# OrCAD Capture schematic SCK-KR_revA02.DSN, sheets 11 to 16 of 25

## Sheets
11 PMOD3&4: size Custom
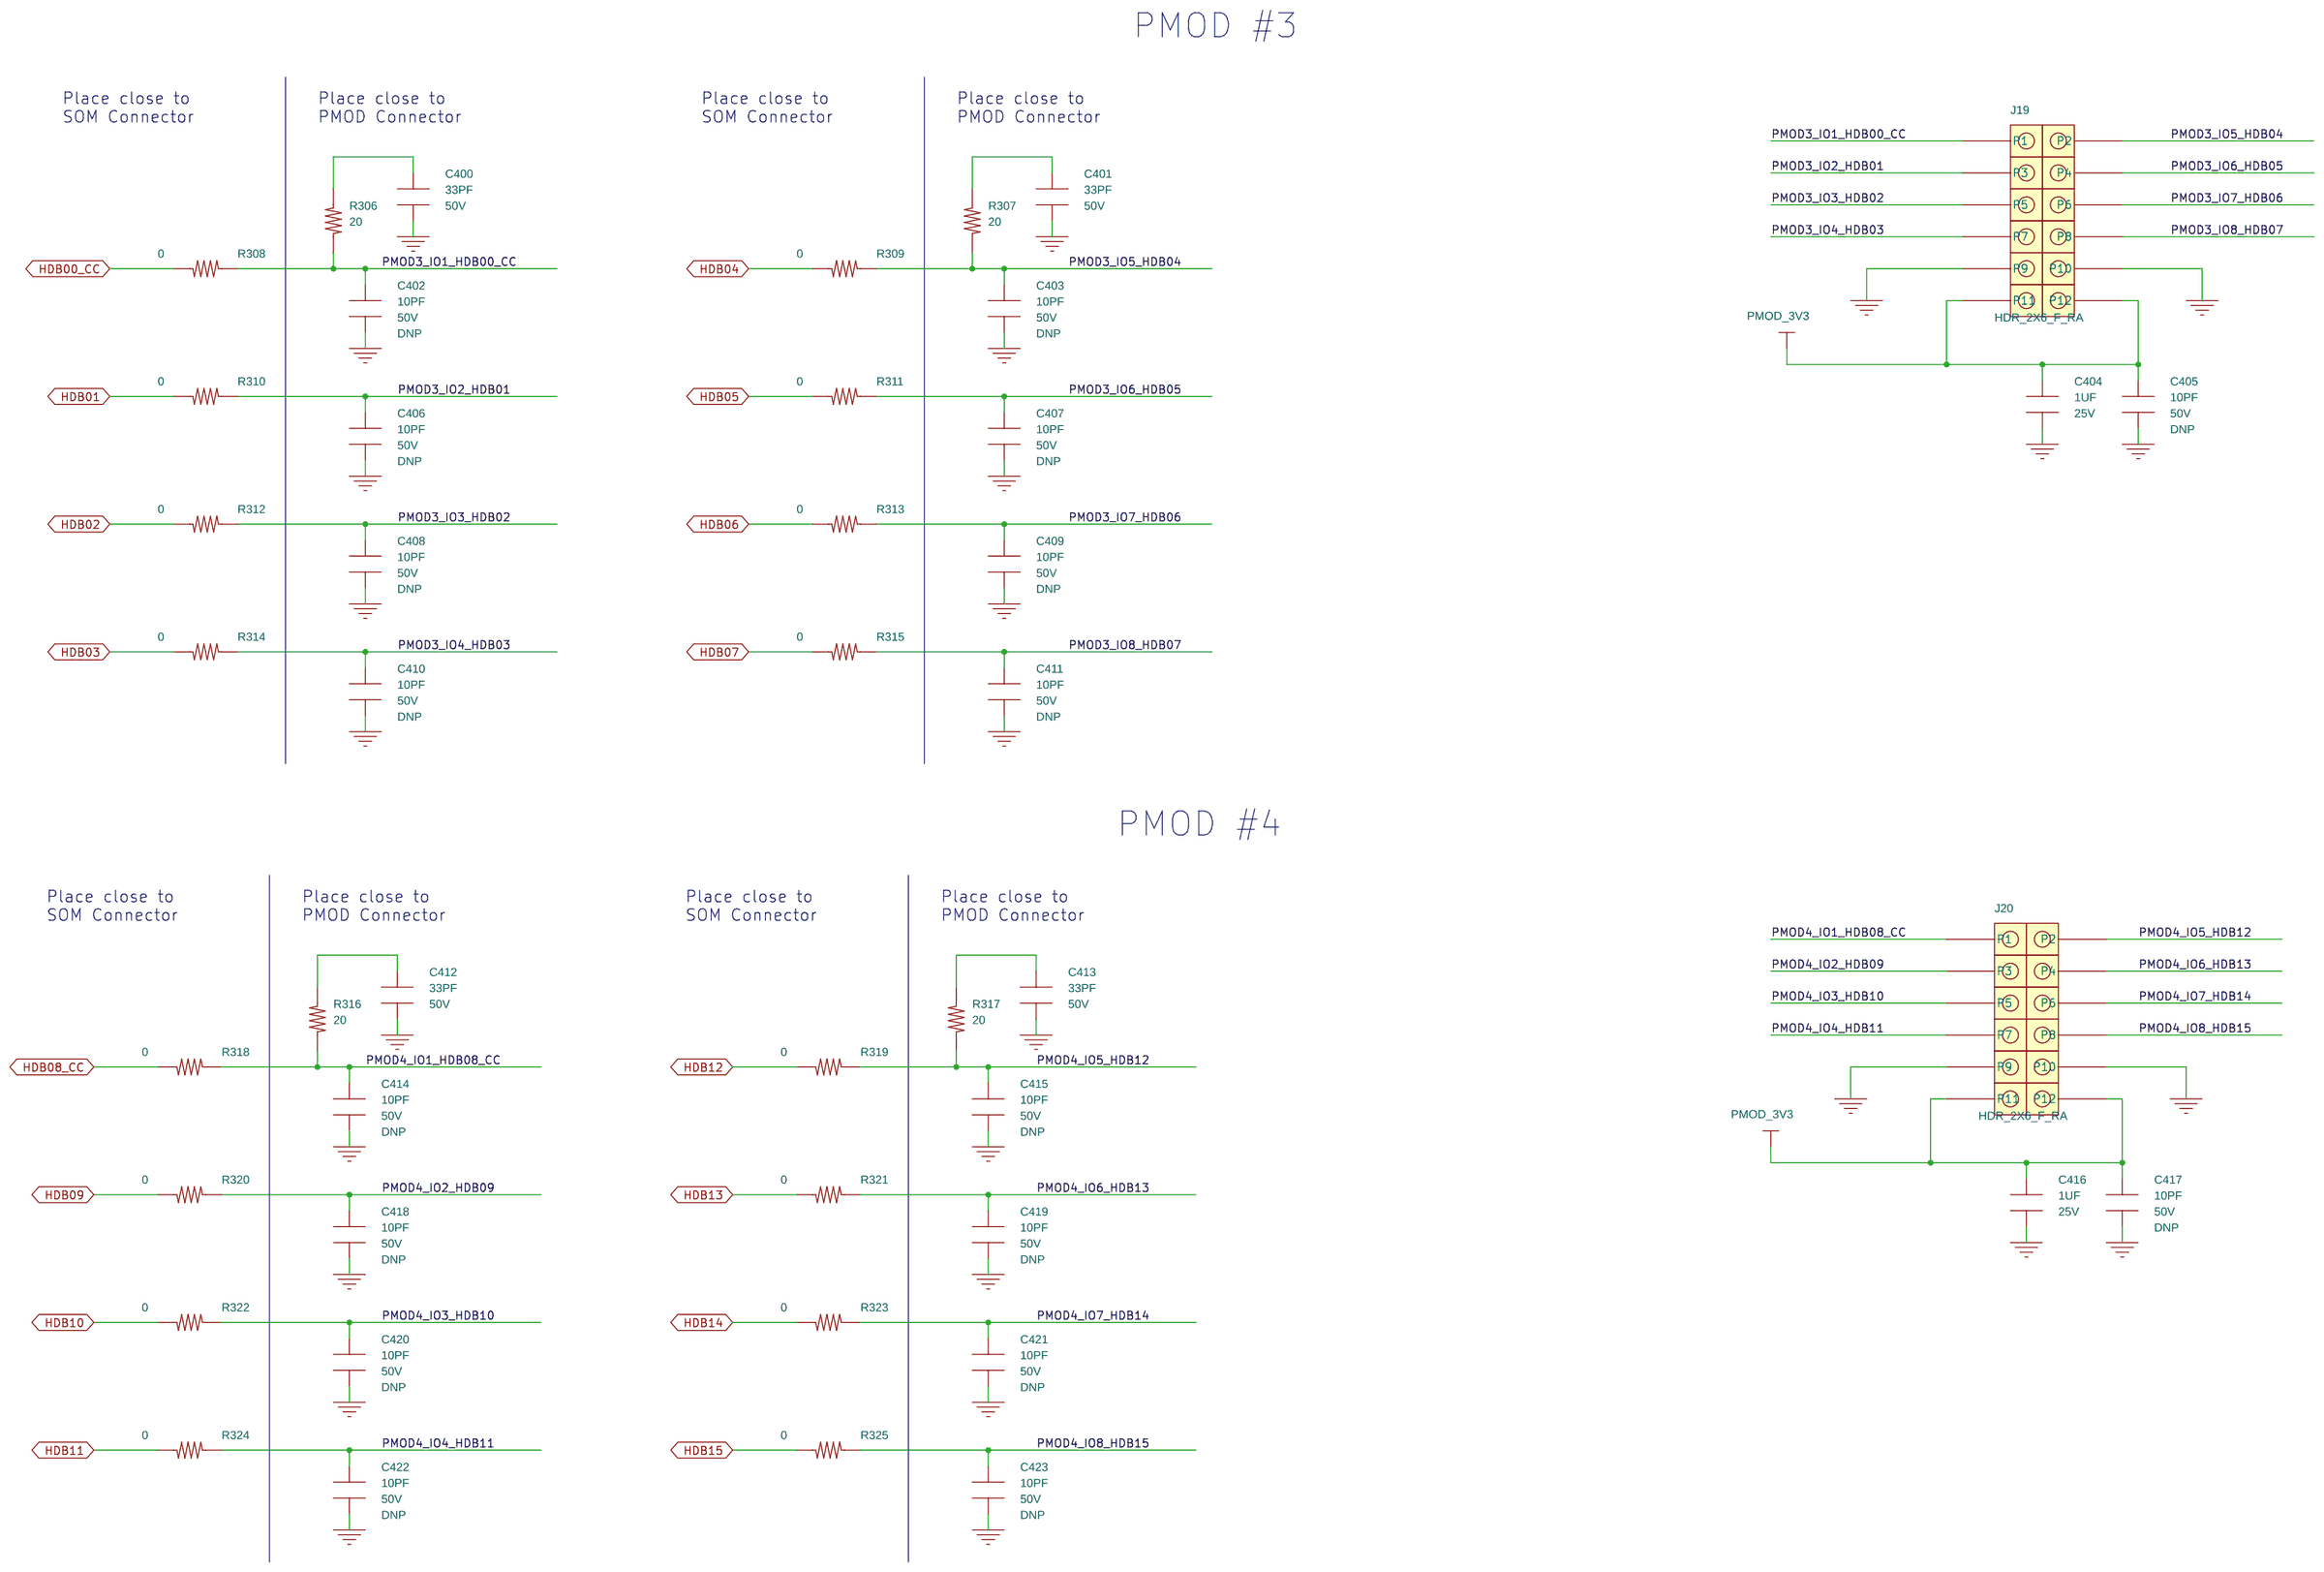
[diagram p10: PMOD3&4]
12 RPI Expansion CONN: size Custom
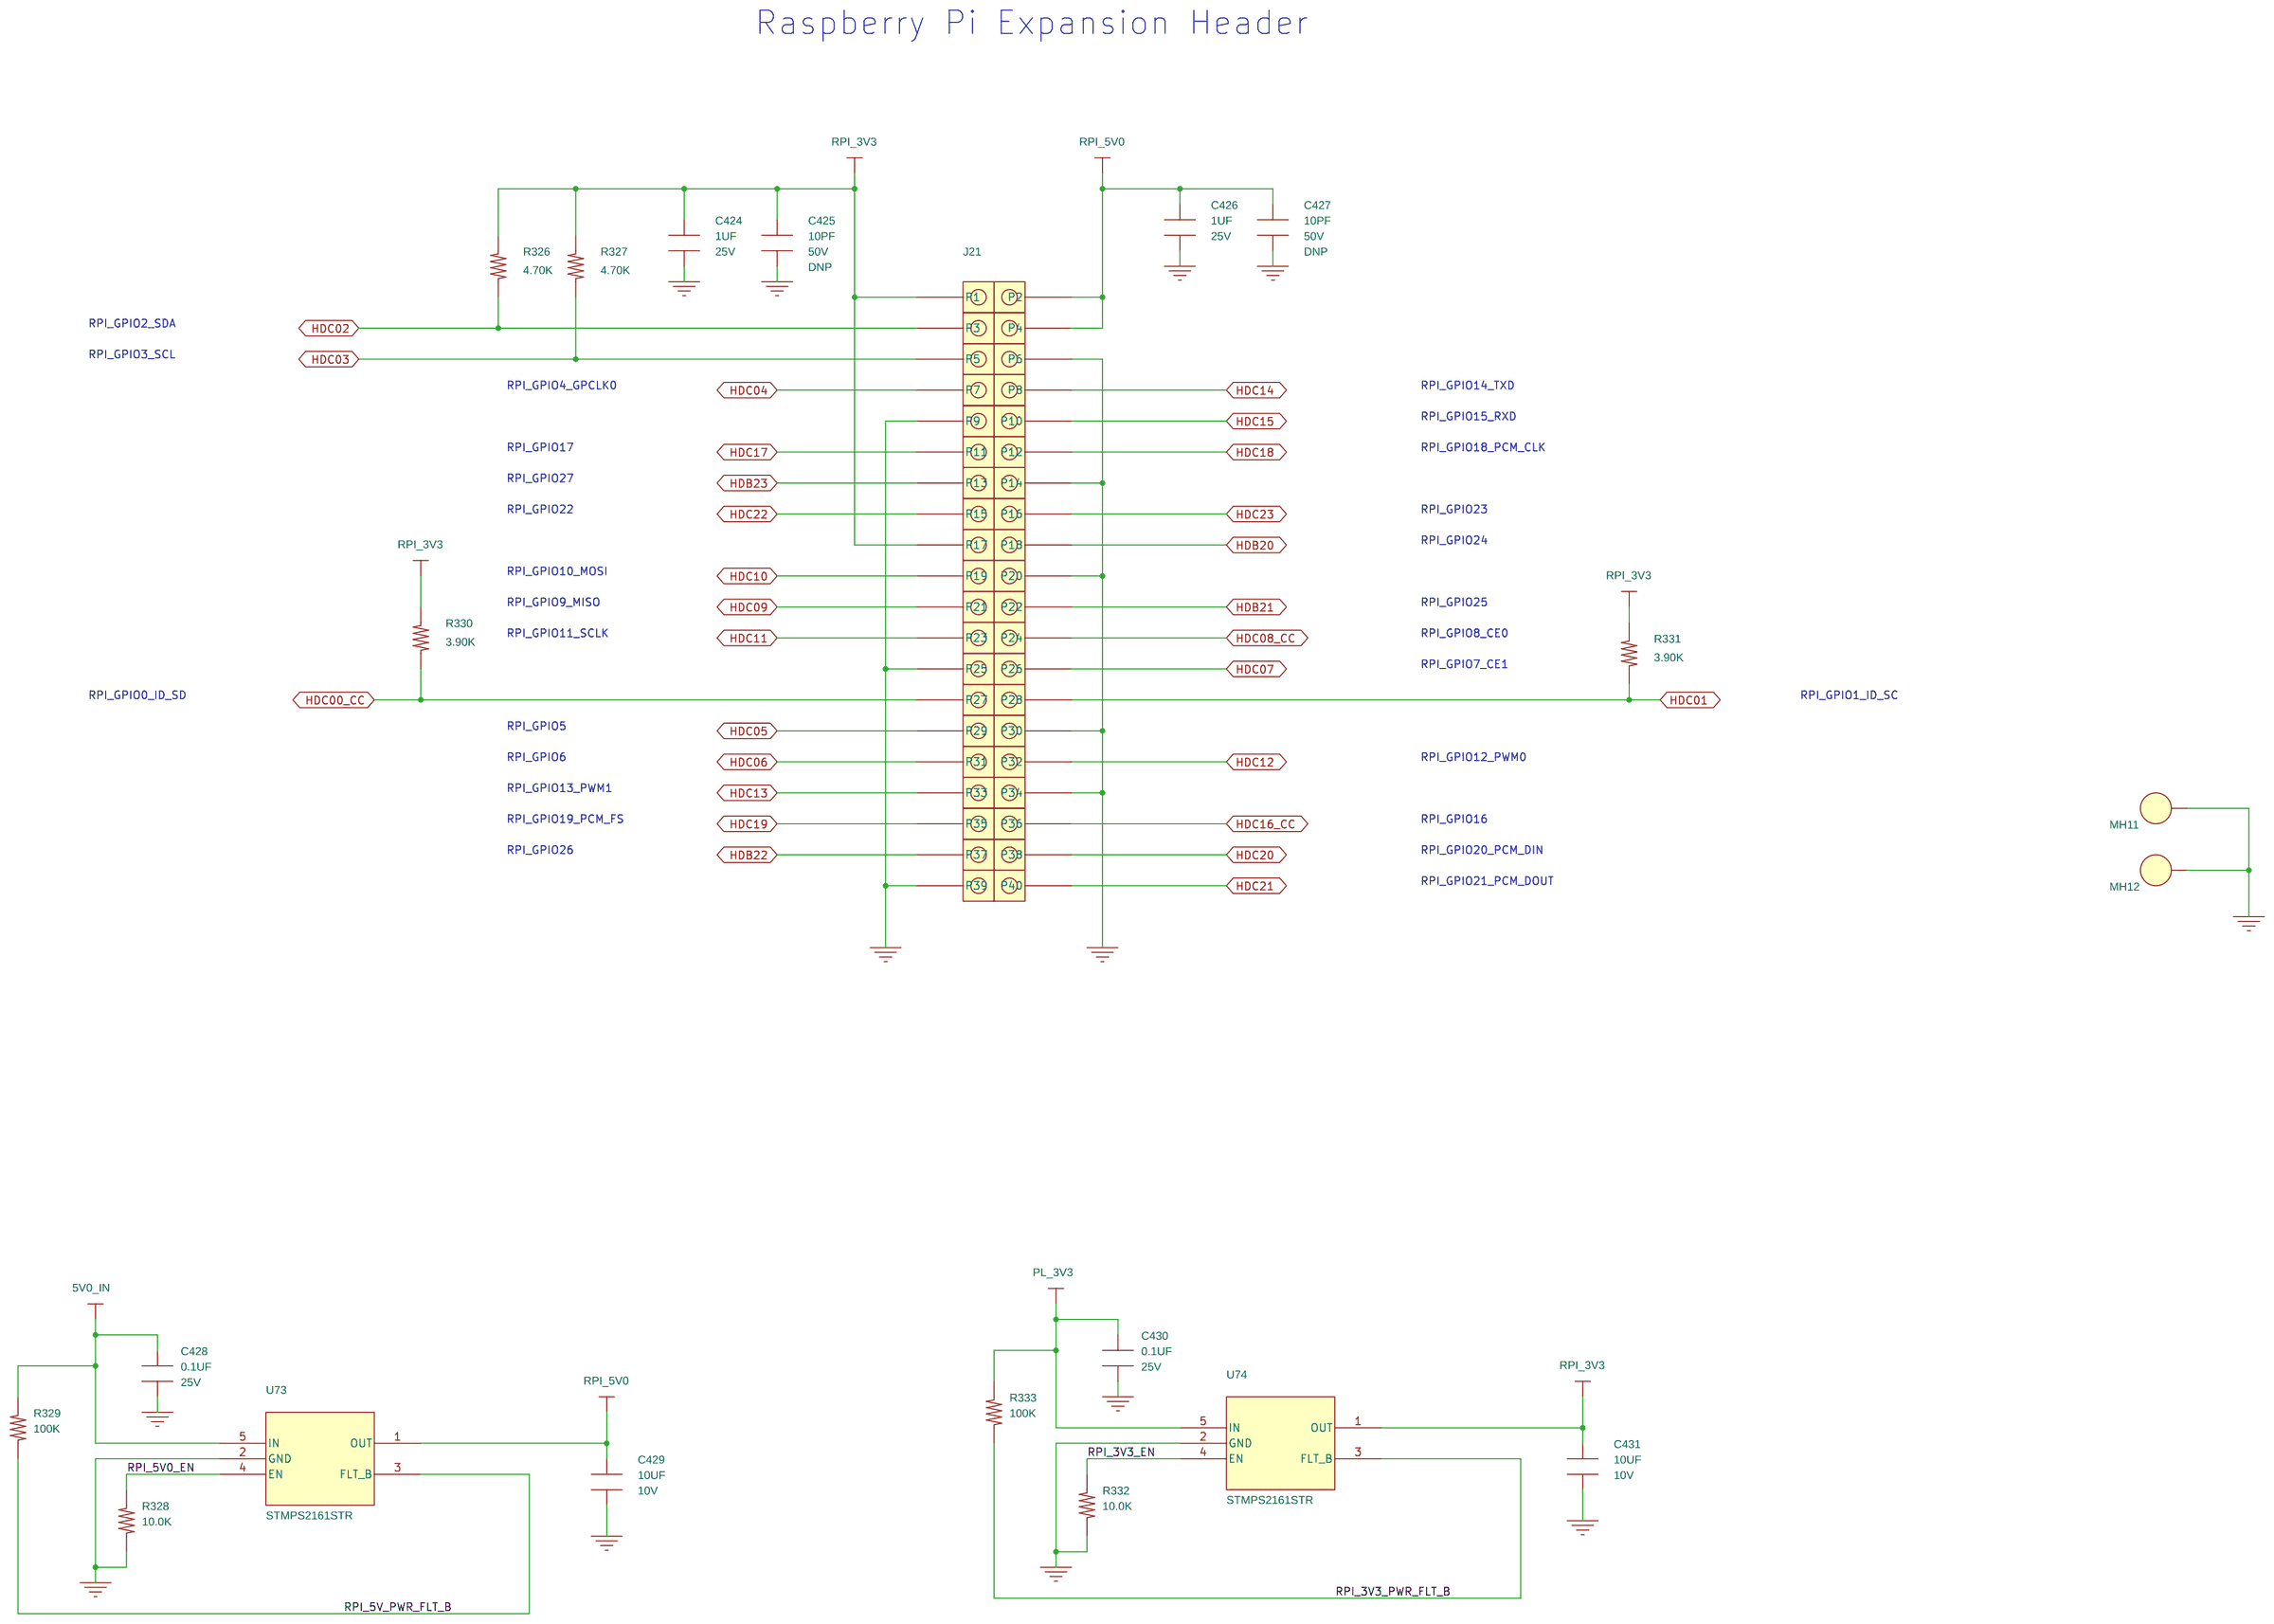
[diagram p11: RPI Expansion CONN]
13 Framos CONN: size Custom
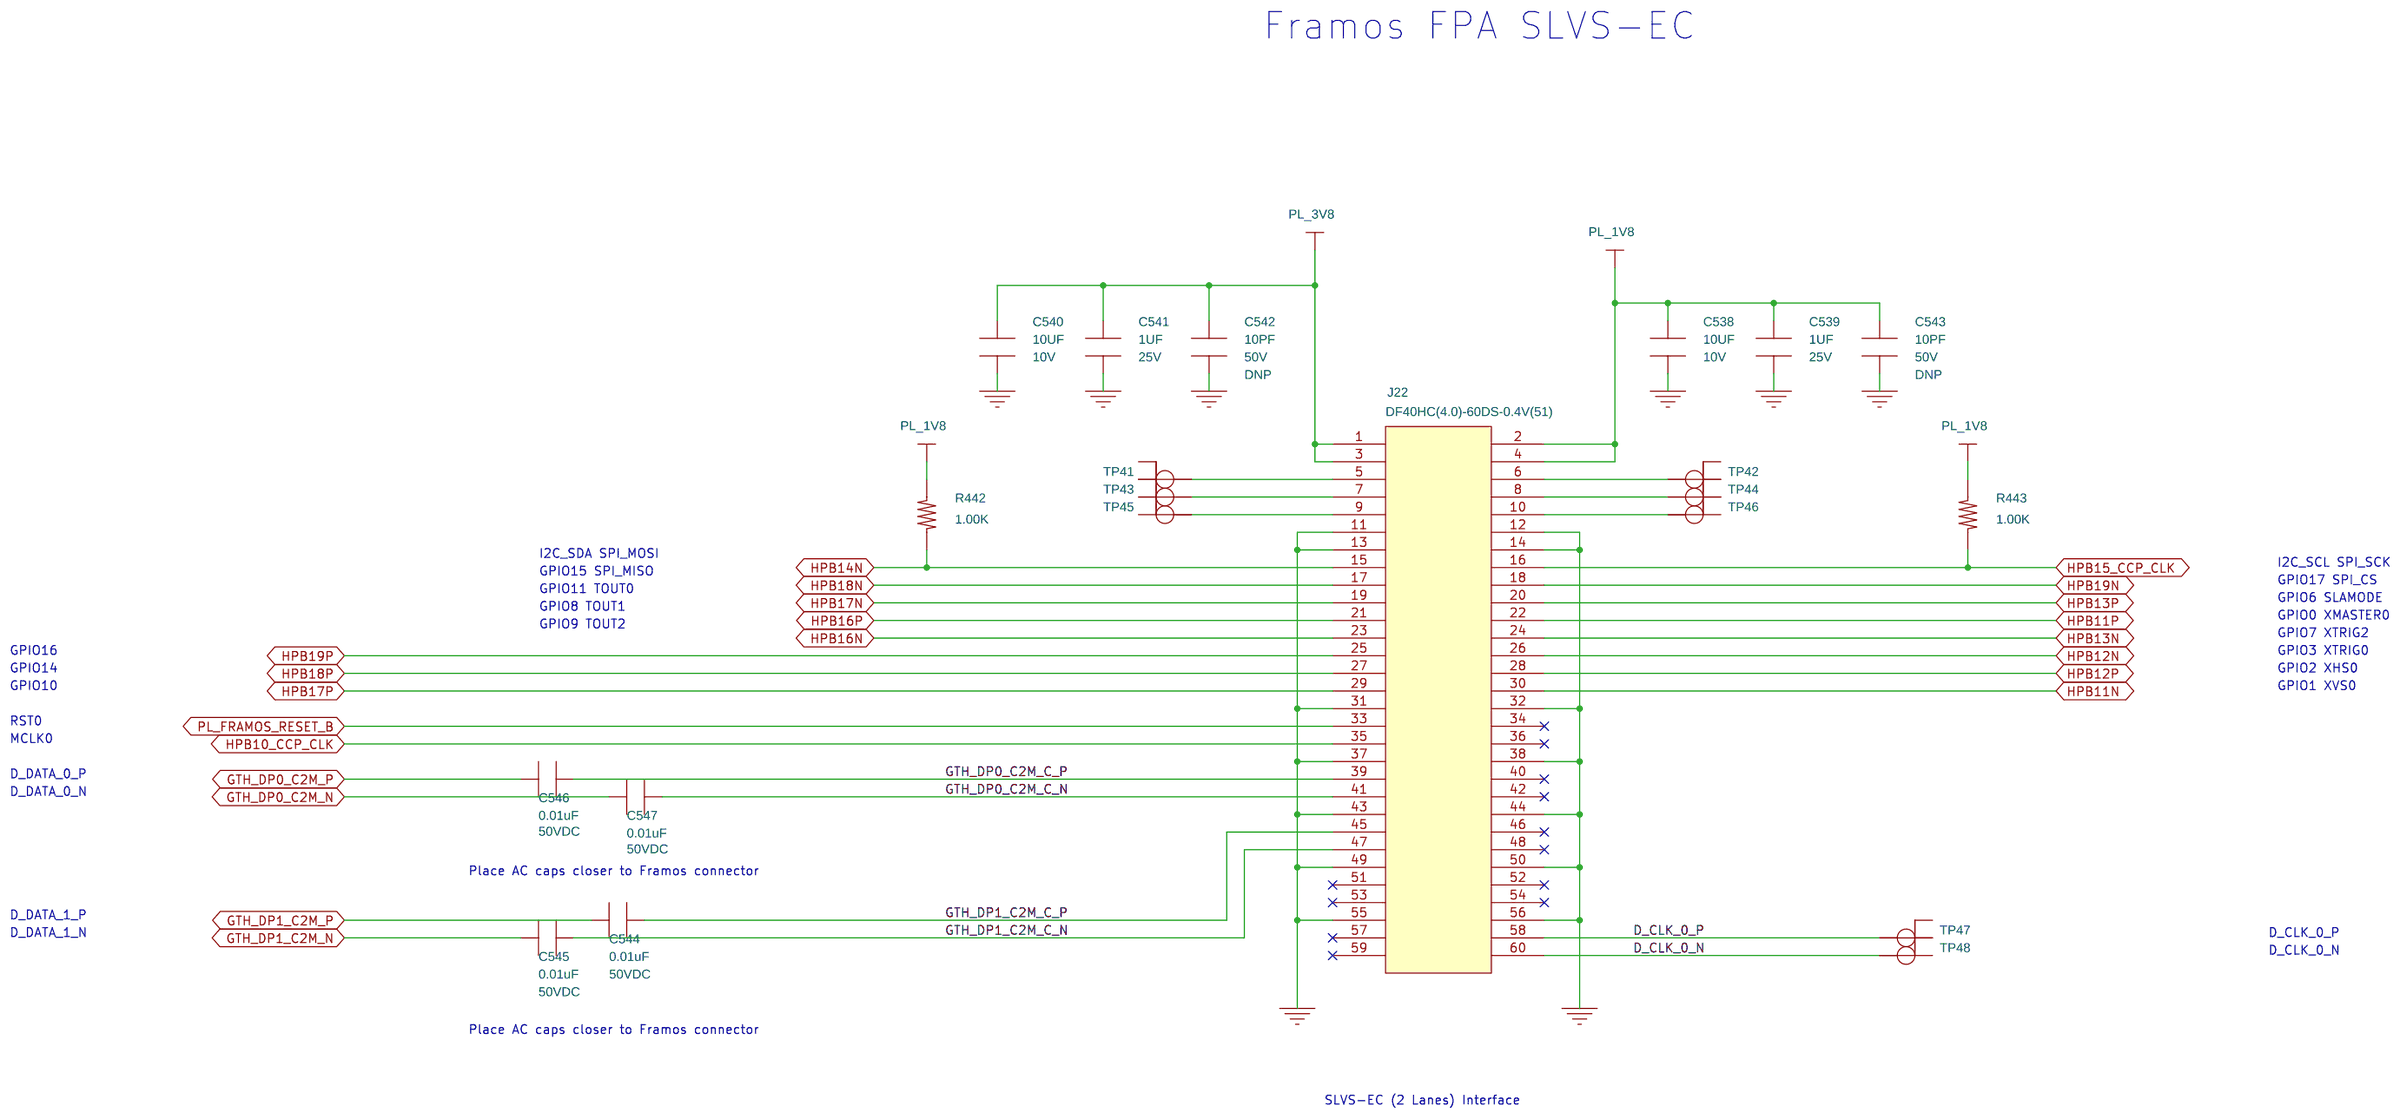
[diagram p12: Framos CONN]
14 SFP+: size Custom
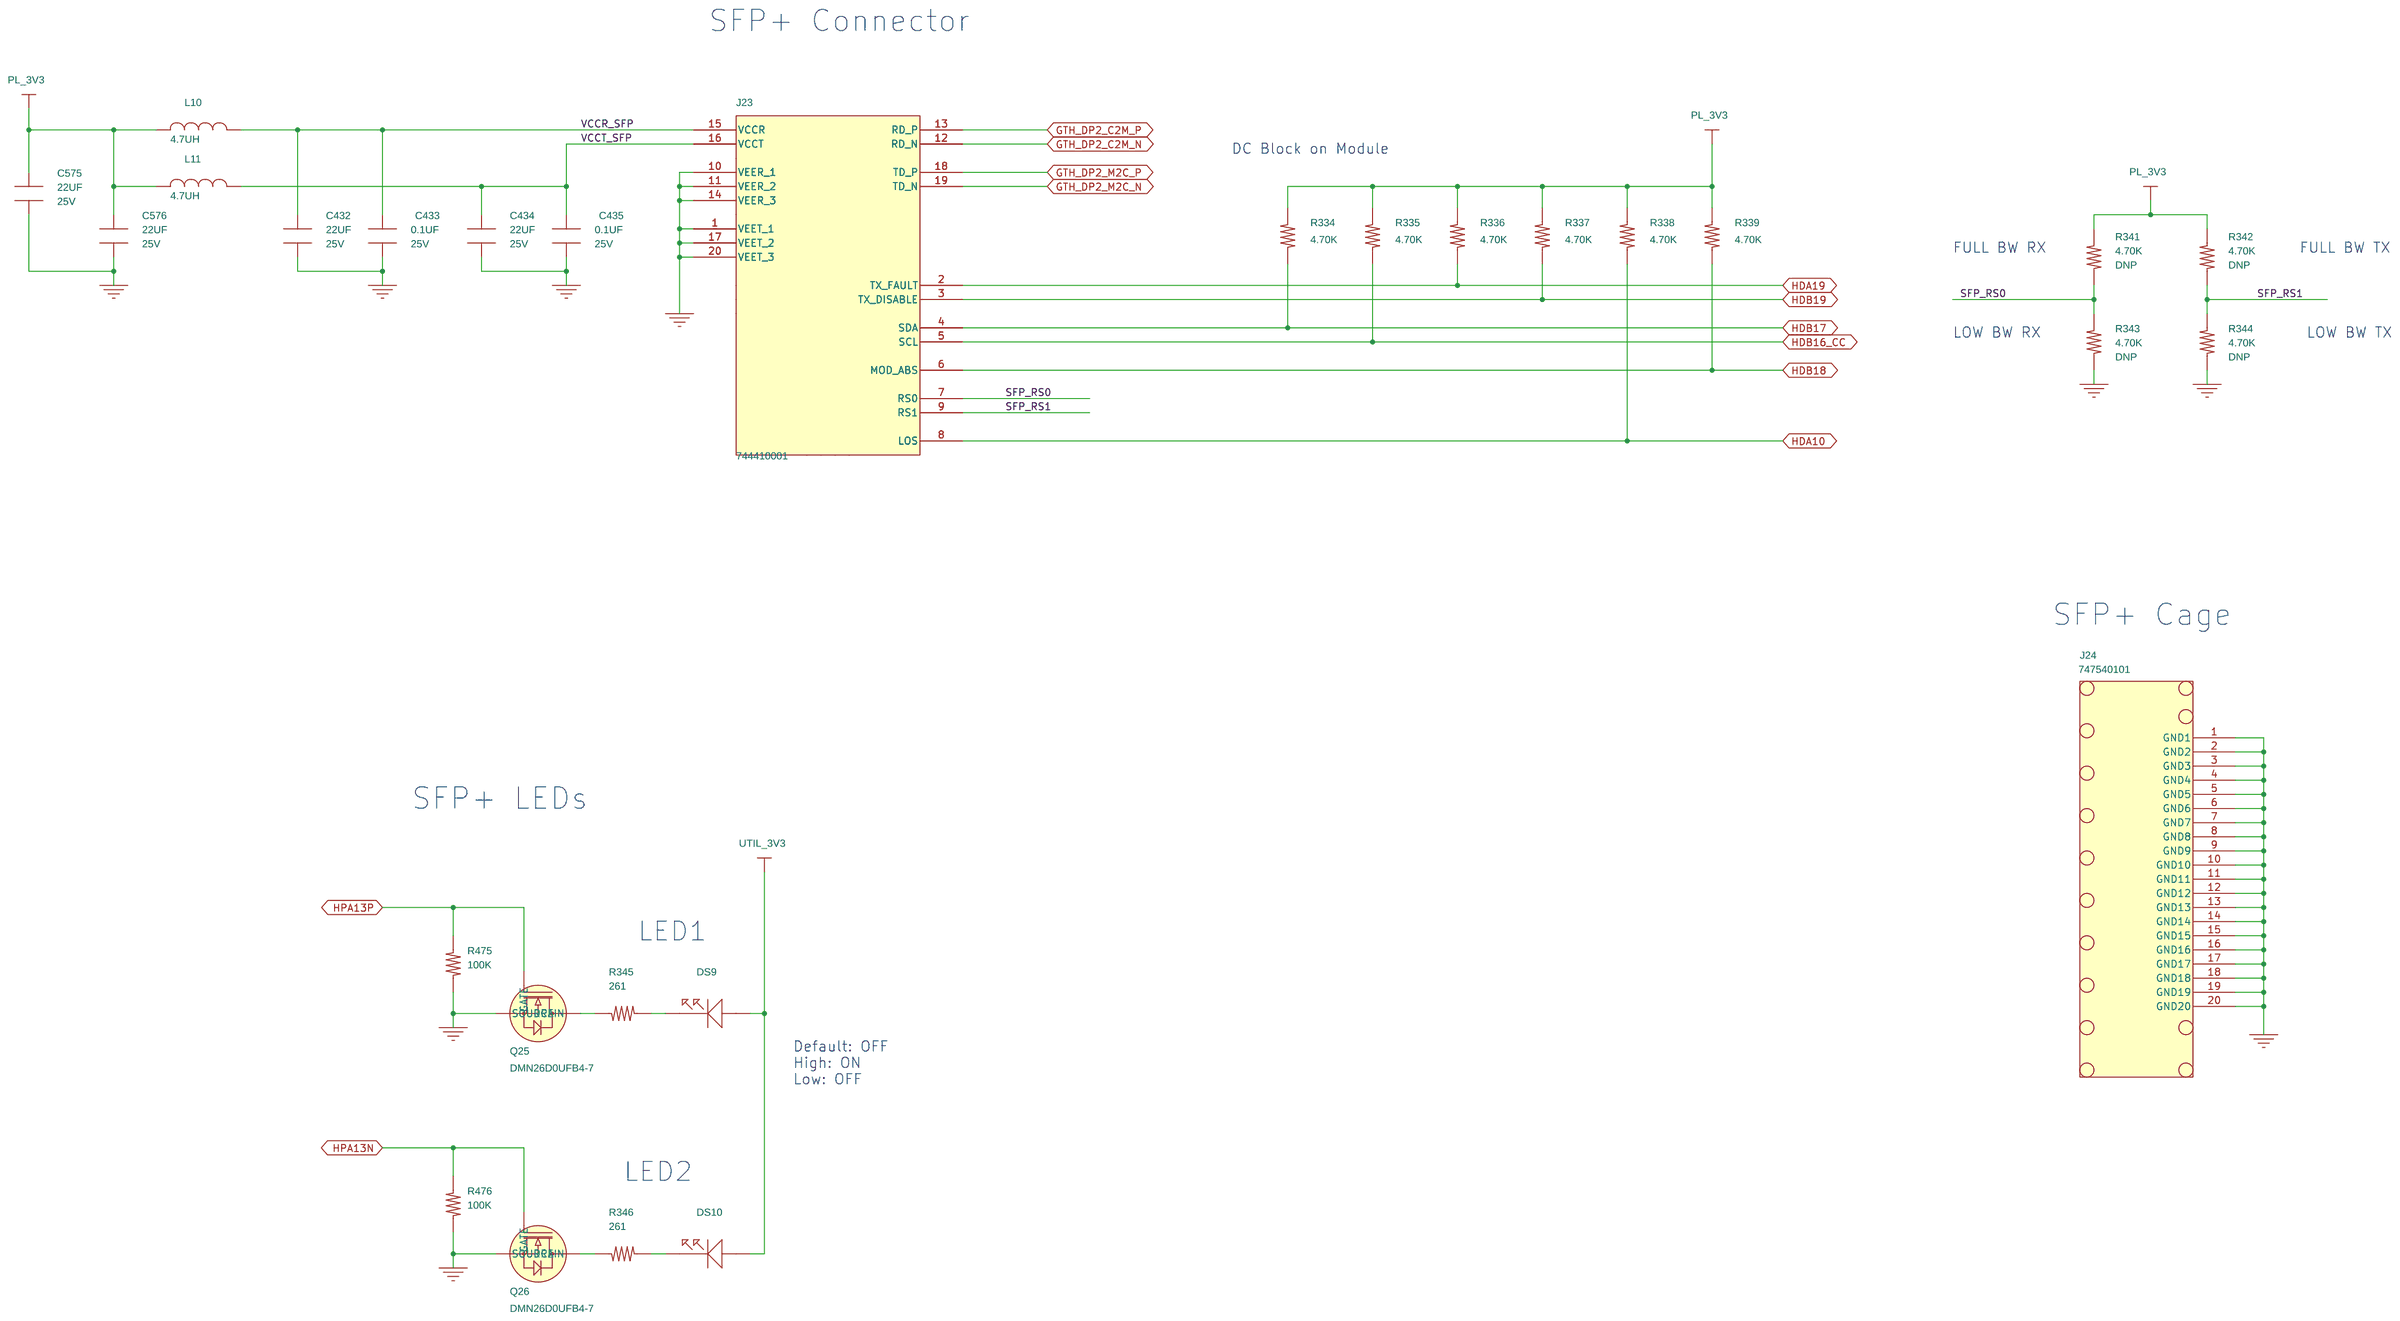
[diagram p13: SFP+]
15 I2C, EEPROM: size Custom
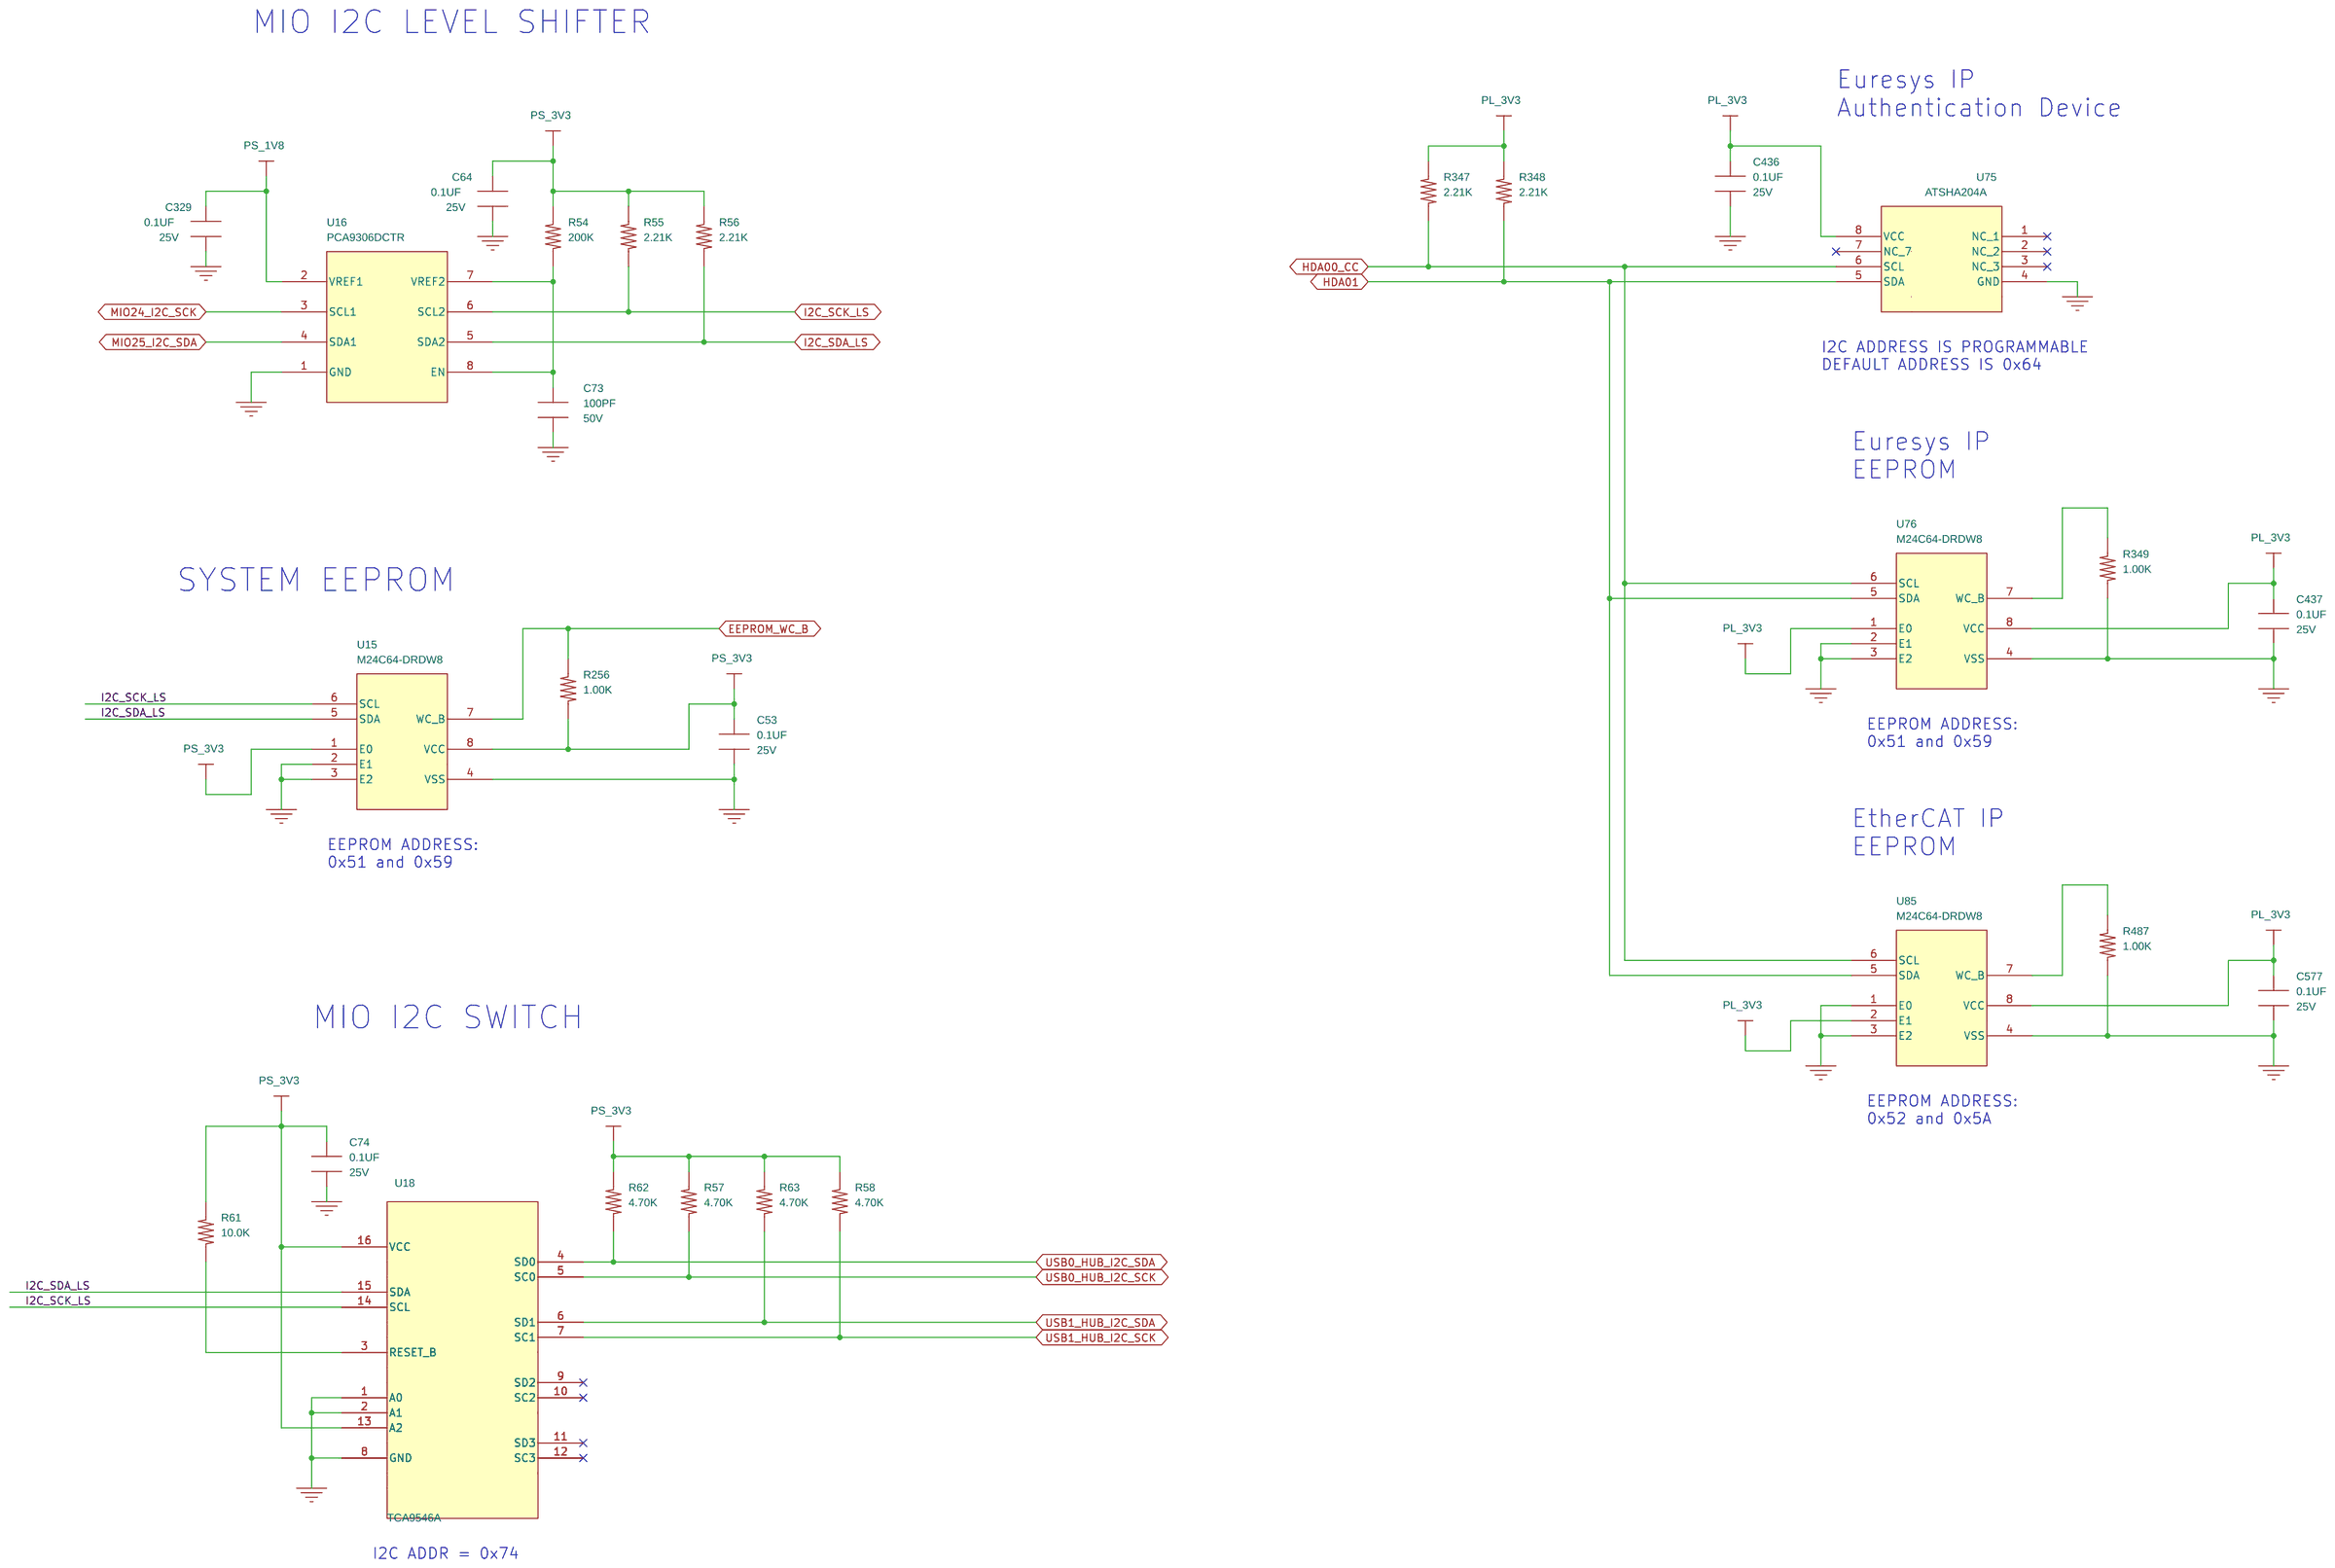
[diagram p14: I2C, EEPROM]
16 16_Clock Gen, Reset: size Custom
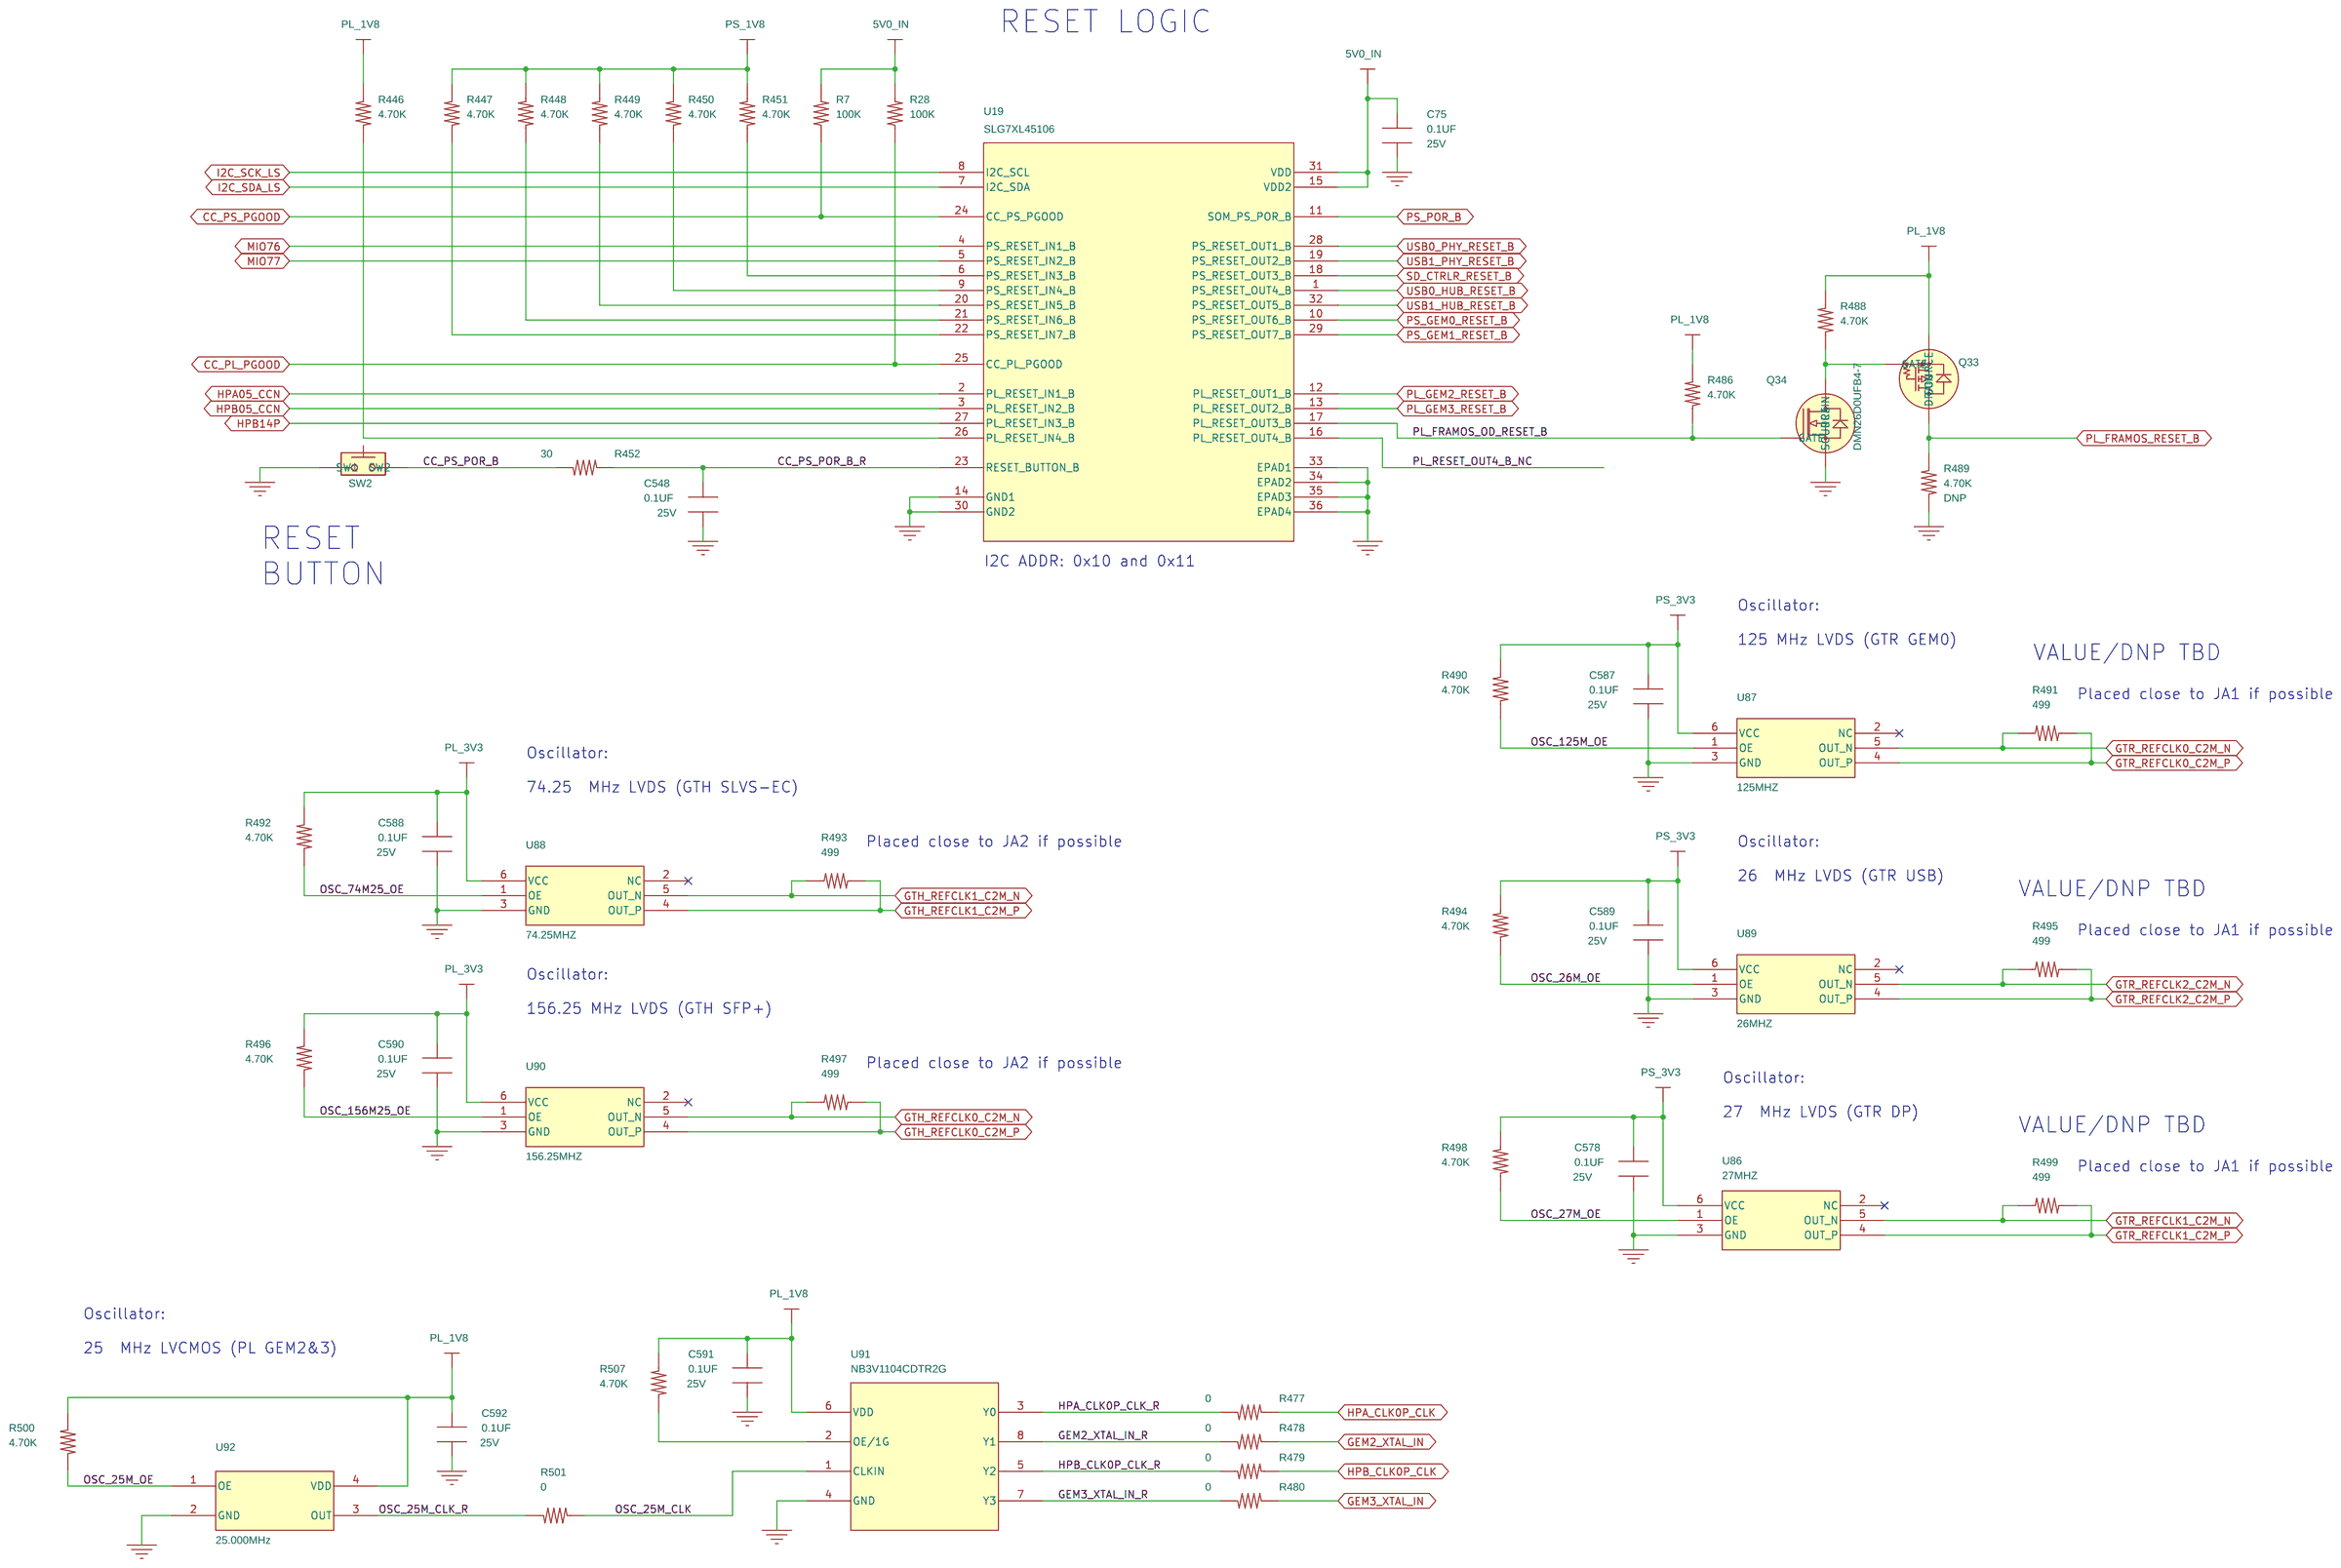
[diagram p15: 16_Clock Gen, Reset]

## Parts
sheet 16_Clock Gen, Reset
C75  0.1UF  [CAPC100X50X55]
C548  0.1UF  [CAPC100X50X55]
C578  0.1UF  [CAPC100X50X55]
C587  0.1UF  [CAPC100X50X55]
C588  0.1UF  [CAPC100X50X55]
C589  0.1UF  [CAPC100X50X55]
C590  0.1UF  [CAPC100X50X55]
C591  0.1UF  [CAPC100X50X55]
C592  0.1UF  [CAPC100X50X55]
Q33  RZM001P02T2L  [SOT_723]
Q34  DMN26D0UFB4-7  [DFN_105X65x40_3]
R7  100K  [RESC100X50X40]
R28  100K  [RESC100X50X40]
R446  4.70K  [RESC100X50X40]
R447  4.70K  [RESC100X50X40]
R448  4.70K  [RESC100X50X40]
R449  4.70K  [RESC100X50X40]
R450  4.70K  [RESC100X50X40]
R451  4.70K  [RESC100X50X40]
R452  30  [RESC100X50X40]
R477  0  [RESC100X50X40]
R478  0  [RESC100X50X40]
R479  0  [RESC100X50X40]
R480  0  [RESC100X50X40]
R486  4.70K  [RESC100X50X40]
R488  4.70K  [RESC100X50X40]
R489  4.70K  [RESC100X50X40]
R490  4.70K  [RESC100X50X40]
R491  499  [RESC100X50X40]
R492  4.70K  [RESC100X50X40]
R493  499  [RESC100X50X40]
R494  4.70K  [RESC100X50X40]
R495  499  [RESC100X50X40]
R496  4.70K  [RESC100X50X40]
R497  499  [RESC100X50X40]
R498  4.70K  [RESC100X50X40]
R499  499  [RESC100X50X40]
R500  4.70K  [RESC100X50X40]
R501  0  [RESC100X50X40]
R507  4.70K  [RESC100X50X40]
SW2  B3U-1000P  [SW_OMRON_2P]
U19  SLG7XL45106  [STQFN04P400x400x60_32_270]
U86  27MHZ  [osc_ral_500x320x154]
U87  125MHZ  [osc_ral_500x320x154]
U88  74.25MHZ  [osc_ral_500x320x154]
U89  26MHZ  [osc_ral_500x320x154]
U90  156.25MHZ  [osc_ral_500x320x154]
U91  NB3V1104CDTR2G  [TSSOP8_65p450x310x120]
U92  25.000MHz  [OSC_330x260x120_4_RAL]
sheet Framos CONN
C538  10UF  [CAPC100X50X70]
C539  1UF  [CAPC100X50X70]
C540  10UF  [CAPC100X50X70]
C541  1UF  [CAPC100X50X70]
C542  10PF  [CAPC100X50X55]
C543  10PF  [CAPC100X50X55]
C544  0.01uF  [CAPC100X50X55]
C545  0.01uF  [CAPC100X50X55]
C546  0.01uF  [CAPC100X50X55]
C547  0.01uF  [CAPC100X50X55]
J22  DF40HC(4.0)-60DS-0.4V(51)  [CON_HIROSE_DF40HC_4P0_60DS_04V]
R442  1.00K  [RESC100X50X40]
R443  1.00K  [RESC100X50X40]
TP41  TP_PAD  [TP_PAD]
TP42  TP_PAD  [TP_PAD]
TP43  TP_PAD  [TP_PAD]
TP44  TP_PAD  [TP_PAD]
TP45  TP_PAD  [TP_PAD]
TP46  TP_PAD  [TP_PAD]
TP47  TP_PAD  [TP_PAD]
TP48  TP_PAD  [TP_PAD]
sheet I2C, EEPROM
C53  0.1UF  [CAPC100X50X55]
C64  0.1UF  [CAPC100X50X55]
C73  100PF  [CAPC100X50X55]
C74  0.1UF  [CAPC100X50X55]
C329  0.1UF  [CAPC100X50X55]
C436  0.1UF  [CAPC100X50X55]
C437  0.1UF  [CAPC100X50X55]
C577  0.1UF  [CAPC100X50X55]
R54  200K  [RESC100X50X40]
R55  2.21K  [RESC100X50X40]
R56  2.21K  [RESC100X50X40]
R57  4.70K  [RESC100X50X40]
R58  4.70K  [RESC100X50X40]
R61  10.0K  [RESC100X50X40]
R62  4.70K  [RESC100X50X40]
R63  4.70K  [RESC100X50X40]
R256  1.00K  [RESC100X50X40]
R347  2.21K  [RESC100X50X40]
R348  2.21K  [RESC100X50X40]
R349  1.00K  [RESC100X50X40]
R487  1.00K  [RESC100X50X40]
U15  M24C64-DRDW8  [TSSOP8_65P440X300MM]
U16  PCA9306DCTR  [DCT_R_PDSO_G8]
U18  TCA9546A  [SOP65P640X120-16]
U75  ATSHA204A  [UDFN05P200X300X55-8_150X130]
U76  M24C64-DRDW8  [TSSOP8_65P440X300MM]
U85  M24C64-DRDW8  [TSSOP8_65P440X300MM]
sheet PMOD3&4
C400  33PF  [CAPC100X50X56]
C401  33PF  [CAPC100X50X56]
C402  10PF  [CAPC100X50X55]
C403  10PF  [CAPC100X50X55]
C404  1UF  [CAPC100X50X70]
C405  10PF  [CAPC100X50X55]
C406  10PF  [CAPC100X50X55]
C407  10PF  [CAPC100X50X55]
C408  10PF  [CAPC100X50X55]
C409  10PF  [CAPC100X50X55]
C410  10PF  [CAPC100X50X55]
C411  10PF  [CAPC100X50X55]
C412  33PF  [CAPC100X50X56]
C413  33PF  [CAPC100X50X56]
C414  10PF  [CAPC100X50X55]
C415  10PF  [CAPC100X50X55]
C416  1UF  [CAPC100X50X70]
C417  10PF  [CAPC100X50X55]
C418  10PF  [CAPC100X50X55]
C419  10PF  [CAPC100X50X55]
C420  10PF  [CAPC100X50X55]
C421  10PF  [CAPC100X50X55]
C422  10PF  [CAPC100X50X55]
C423  10PF  [CAPC100X50X55]
J19  HDR_2X6_F_RA  [HDR_F2X6_PMOD]
J20  HDR_2X6_F_RA  [HDR_F2X6_PMOD]
R306  20  [RESC100X50X40]
R307  20  [RESC100X50X40]
R308  0  [RESC100X50X40]
R309  0  [RESC100X50X40]
R310  0  [RESC100X50X40]
R311  0  [RESC100X50X40]
R312  0  [RESC100X50X40]
R313  0  [RESC100X50X40]
R314  0  [RESC100X50X40]
R315  0  [RESC100X50X40]
R316  20  [RESC100X50X40]
R317  20  [RESC100X50X40]
R318  0  [RESC100X50X40]
R319  0  [RESC100X50X40]
R320  0  [RESC100X50X40]
R321  0  [RESC100X50X40]
R322  0  [RESC100X50X40]
R323  0  [RESC100X50X40]
R324  0  [RESC100X50X40]
R325  0  [RESC100X50X40]
sheet RPI Expansion CONN
C424  1UF  [CAPC100X50X70]
C425  10PF  [CAPC100X50X55]
C426  1UF  [CAPC100X50X70]
C427  10PF  [CAPC100X50X55]
C428  0.1UF  [CAPC100X50X55]
C429  10UF  [CAPC100X50X70]
C430  0.1UF  [CAPC100X50X55]
C431  10UF  [CAPC100X50X70]
J21  HDR_2X20  [HDR_2X20]
MH11  Mh_NP_C275  [Mh_NP_C275]
MH12  Mh_NP_C275  [Mh_NP_C275]
R326  4.70K  [RESC100X50X40]
R327  4.70K  [RESC100X50X40]
R328  10.0K  [RESC100X50X40]
R329  100K  [RESC100X50X40]
R330  3.90K  [RESC100X50X40]
R331  3.90K  [RESC100X50X40]
R332  10.0K  [RESC100X50X40]
R333  100K  [RESC100X50X40]
U73  STMPS2161STR  [SOT95P280X145_5]
U74  STMPS2161STR  [SOT95P280X145_5]
sheet SFP+
C432  22UF  [CAPC200X125X145]
C433  0.1UF  [CAPC100X50X55]
C434  22UF  [CAPC200X125X145]
C435  0.1UF  [CAPC100X50X55]
C575  22UF  [CAPC200X125X145]
C576  22UF  [CAPC200X125X145]
DS9  LED-GRN-SMT  [LED_0603]
DS10  LED-GRN-SMT  [LED_0603]
J23  744410001  [CON_MOLEX_744410001]
J24  747540101  [CAGE_MOLEX_0747540101_L_PIPE]
L10  4.7UH  [IND_IHLP2020BZ_ER]
L11  4.7UH  [IND_IHLP2020BZ_ER]
Q25  DMN26D0UFB4-7  [DFN_105X65x40_3]
Q26  DMN26D0UFB4-7  [DFN_105X65x40_3]
R334  4.70K  [RESC100X50X40]
R335  4.70K  [RESC100X50X40]
R336  4.70K  [RESC100X50X40]
R337  4.70K  [RESC100X50X40]
R338  4.70K  [RESC100X50X40]
R339  4.70K  [RESC100X50X40]
R341  4.70K  [RESC100X50X40]
R342  4.70K  [RESC100X50X40]
R343  4.70K  [RESC100X50X40]
R344  4.70K  [RESC100X50X40]
R345  261  [RESC100X50X40]
R346  261  [RESC100X50X40]
R475  100K  [RESC100X50X40]
R476  100K  [RESC100X50X40]

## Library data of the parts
C53 C64 C74 C75 C329 C428 C430 C436 C437 C548 C577 C578 C587-C592 = CAP_NP: Cap Cer 100nF 10% 25V X5R 0402; ALT_SYMBOLS: CAPC100X50X55RND; Agile Part Number: CAP-00068-01; CIP Link: http://xsjbrdwin1/CIP-E/Component/Index/All?pn=100040; DEVICE: 0_1UF_0402_X7R_50V; Dielectric: X7R; Dielectric Type: X5R; MANF: TAIYO YUDEN; MANF_P/N: UMK105B7104KV-FR; Manufacturer: TAIYO YUDEN; Manufacturer PN: TMK105BJ104KV-F; OWNER: 6176; PRICE: 0.02; Part Type: CERAMIC; PartType: CERAMIC; ROHS: Yes; Tolerance: 10%; Voltage: 25V; barcode: 100040
Q33 = RZM001P02T2L: MOSFET P-Ch 20V 100mA 3.8R SOT-723; Agile Part Number: TRN-00043-01; Barcode: 83000001; CIP Link: http://xsjbrdwin1/CIP-E/Component/Index/All?pn=83000001; Part Type: PCh-FET; Rated Power: 150mW (Ta)
Q25 Q26 Q34 = DMN26D0UFB4: MOSFET N-CH 20V 230MA DFN; Agile Part Number: TRN-00054-01; Barcode: 83000008; CIP Link: http://xsjbrdwin1/CIP-E/Component/Index/All?pn=83000008; Manufacturer: Diodes Incorporated; Part Type: FET; Rated Power: 350mW (Ta); Datasheet: https://www.diodes.com/assets/Datasheets/ds31775.pdf
R7 R28 R475 R476 = RES: Res 100K 5% 1/16W 200PPM 50V 0402; Agile Part Number: RES-00137-01; Barcode: 200127; CIP Link: http://xsjbrdwin1/CIP-E/Component/Index/All?pn=200127; Manufacturer: PANASONIC; Manufacturer PN: ERJ2GEJ104X; Part Type: SMT - 5%; Rated Power: 1/16W; Tolerance: 5%
R326 R327 R334-R339 R446-R451 R486 R488 R490 R492 R494 R496 R498 R500 R507 = RES: Res 4K7 1% 1/16W 100PPM 50V 0402; ALT_SYMBOLS: RESC100X50X40RND; Agile Part Number: RES-00035-01; Barcode: 200067; CIP Link: http://xsjbrdwin1/CIP-E/Component/Index/All?pn=200067; Manufacturer: PANASONIC; Manufacturer PN: ERJ2RKF4701X; OWNER: 3670; PRICE: 0.01; Part Type: SMT - 1%; PartType: SMT - 1%; Power: 1/16W; ROHS: Yes; Rated Power: 1/16W; Tolerance: 1%; primarykey: 128
R452 = RES: Res 30R 1% 1/16W 100PPM 50V 0402; Agile Part Number: RES-00143-01; Barcode: 200133; CIP Link: http://xsjbrdwin1/CIP-E/Component/Index/All?pn=200133; Manufacturer: PANASONIC; Manufacturer PN: ERJ2RKF30R0X; Part Type: SMT - 1%; Rated Power: 1/16W; Tolerance: 1%
R308-R315 R318-R325 R477-R480 R501 = RES: Res 0R 50mR 1A 0402; ALT_SYMBOLS: RESC100X50X40RND; Agile Part Number: RES-00010-01; Barcode: 200012; CIP Link: http://xsjbrdwin1/CIP-E/Component/Index/All?pn=200012; Manufacturer: PANASONIC; Manufacturer PN: ERJ2GE0R00X; Part Type: SMT - 5%; Tolerance: 5%
R341-R344 R489 = RES: Res 4K7 1% 1/16W 100PPM 50V 0402; ALT_SYMBOLS: RESC100X50X40RND; ASSEMBLY_OPTIONS: DNP; Agile Part Number: RES-00035-01; Barcode: 200067; CIP Link: http://xsjbrdwin1/CIP-E/Component/Index/All?pn=200067; Manufacturer: PANASONIC; Manufacturer PN: ERJ2RKF4701X; OWNER: 3670; PRICE: 0.01; Part Type: SMT - 1%; PartType: SMT - 1%; Power: 1/16W; ROHS: Yes; Rated Power: 1/16W; Tolerance: 1%; primarykey: 128
R491 R493 R495 R497 R499 = RES: Res 499R 1% 1/16W 100PPM 50V 0402; ALT_SYMBOLS: RESC100X50X40RND; Agile Part Number: RES-00028-01; Barcode: 200071; CIP Link: http://xsjbrdwin1/CIP-E/Component/Index/All?pn=200071; Manufacturer: PANASONIC; Manufacturer PN: ERJ2RKF4990X; Part Type: SMT - 1%; Rated Power: 1/16W; Tolerance: 1%
SW2 = BTN_MOMENT: Switch SPST-NO Mom 50mA 12V 1.6mm H 1.5Nw SMT IP40; Agile Part Number: SWH-00003-01; Barcode: 440024; CIP Link: http://xsjbrdwin1/CIP-E/Component/Index/All?pn=440024; Manufacturer: OMRON; Part Type: MOMENT
U19 = SLG7XL45106: IC Reset Logic 12 Outs I2C 2.3-5.5V STQFN-32; Agile Part Number: ICS-00875-01; Barcode: 50000322; CIP Link: http://xsjbrdwin1/CIP-E/Component/Index/All?pn=50000322; Part Type: IC
U86 = XCO583IV11-27.000: Osc 27MHz 3.3V 25PPM 15pF 5032 SMT LVDS with OE; Agile Part Number: OSC-00092-01; Barcode: 60000036; CIP Link: http://xsjbrdwin1/CIP-E/Component/Index/All?pn=60000036; Frequency Stability: 25ppm; Part Type: OSCILLATOR; RoHS: YES
U87 = XCO583IV11-27.000: Osc XO 125MHz 3.3V 30PPM 15pF 5032 SMT LVDS with OE; Agile Part Number: OSC-00095-01; Barcode: 60000041; CIP Link: http://xsjbrdwin1/CIP-E/Component/Index/All?pn=60000041; Frequency Stability: 25ppm; Part Type: OSCILLATOR; RoHS: YES
U88 = XCO583IV11-27.000: Osc XO 74.25MHz 3.3V 30PPM 15pF 5032 SMT LVDS with OE; Agile Part Number: OSC-00097-01; Barcode: 60000043; CIP Link: http://xsjbrdwin1/CIP-E/Component/Index/All?pn=60000043; Frequency Stability: 25ppm; Part Type: OSCILLATOR; RoHS: YES
U89 = XCO583IV11-27.000: Osc XO 26MHz 3.3V 30PPM 15pF 5032 SMT LVDS with OE; Agile Part Number: OSC-00094-01; Barcode: 60000040; CIP Link: http://xsjbrdwin1/CIP-E/Component/Index/All?pn=60000040; Frequency Stability: 25ppm; Part Type: OSCILLATOR; RoHS: YES
U90 = XCO583IV11-27.000: Osc XO 156.25MHz 3.3V 30PPM 15pF 5032 SMT LVDS with OE; Agile Part Number: OSC-00096-01; Barcode: 60000042; CIP Link: http://xsjbrdwin1/CIP-E/Component/Index/All?pn=60000042; Frequency Stability: 25ppm; Part Type: OSCILLATOR; RoHS: YES
U91 = NB3V1104CDTR2G: IC Buffer Clk 1 to 4 1.8-3.3V 50mA 250MHz 2nSec TSSOP-8 with OE; Agile Part Number: ICS-00877-01; Barcode: 50000335; CIP Link: http://xsjbrdwin1/CIP-E/Component/Index/All?pn=50000335; Part Type: CLOCK FANOUT BUFFER; Supply Voltage: 1.71V ~ 3.6V
U92 = SIT_4PIN: Osc XO 25MHz 1.8V 25PPM 15pF 3225 SMT CMOS with OE; Agile Part Number: OSC-00098-01; Barcode: 60000044; CIP Link: http://xsjbrdwin1/CIP-E/Component/Index/All?pn=60000044; Part Type: OSCILLATOR; RoHS: YES
C429 C431 C538 C540 = CAP_NP: Cap Cer 10uF 20% 10V X5R 0402; Agile Part Number: CAP-00170-01; Barcode: 100197; CIP Link: http://xsjbrdwin1/CIP-E/Component/Index/All?pn=100197; Dielectric Type: X5R; Manufacturer: SAMSUNG; Manufacturer PN: CL05A106MP5NUNC; Part Type: CERAMIC; Tolerance: 20%; Voltage: 10V
C404 C416 C424 C426 C539 C541 = CAP_NP: Cap Cer 1uF 10% 25V X6S 0402; ALT_SYMBOLS: CAPC100X50X55RND; Agile Part Number: CAP-00009-01; Barcode: 100269; CIP Link: http://xsjbrdwin1/CIP-E/Component/Index/All?pn=100269; Dielectric Type: X6S; Manufacturer: MURATA; Manufacturer PN: GRM155C81E105KE11D; Part Type: CERAMIC; Tolerance: 10%; Voltage: 25V
C402 C403 C405-C411 C414 C415 C417-C423 C425 C427 C542 C543 = CAP_NP: Cap Cer 10pF 5% 50V C0G 0402; ALT_SYMBOLS: (0402,C402-25,CAPC100X50X55L25NRND,CAPC100X50X55L30NRND,CAPC100X50X55L30N); ASSEMBLY_OPTIONS: DNP; Agile Part Number: CAP-00115-01; Barcode: 100127; CIP Link: http://xsjbrdwin1/CIP-E/Component/Index/All?pn=100127; Dielectric Type: C0G, NP0; Manufacturer: MURATA; Manufacturer PN: GCM1555C1H100JA16D; Part Type: CERAMIC; Tolerance: 5%; Voltage: 50V
C544-C547 = CAP_NP: Cap Cer 10nF 10% 50V X7R 0402; ALT_SYMBOLS: CAPC100X50X55RND; Agile Part Number: CAP-00031-01; CIP Link: http://xsjbrdwin1/CIP-E/Component/Index/All?pn=100003; Dielectric Type: X7R; Manufacturer: Yageo; Manufacturer PN: CC0402KRX7R9BB103; OWNER: 4001; PRICE: 0; Part Type: CERAMIC; PartType: CERAMIC; ROHS: Yes; Tolerance: 10%; Voltage: 50VDC; barcode: 100003; Datasheet: http://download.siliconexpert.com/pdfs/2017/7/31/11/40/26/700/yageo_/manual/1073881636569039upy-gphc_x7r_6.3v-to-50v_18.pdf
J22 = DF40HC_4.0_-60DS-0.4V: CONN RCPT 60POS SMD GOLD; Agile Part Number: CON-00473-01; Barcode: 40000146; CIP Link: http://xsjbrdwin1/CIP-E/Component/Index/All?pn=40000146; Number of Pins: 60; Part Type: RECEPTACLE; Pitch: 0.016" (0.40mm)
R442 R443 = RES: Res 1K 1% 1/16W 100PPM 50V 0402; ALT_SYMBOLS: RESC100X50X40RND; Agile Part Number: RES-00027-01; Barcode: 200098; CIP Link: http://xsjbrdwin1/CIP-E/Component/Index/All?pn=200098; Manufacturer: PANASONIC; Manufacturer PN: ERJ2RKF4701X; OWNER: 3670; PRICE: 0.01; Part Type: SMT - 1%; PartType: SMT - 1%; Power: 1/16W; ROHS: Yes; Rated Power: 1/16W; Tolerance: 1%; primarykey: 128
TP41-TP48 = TP: TEST POINT 24mil SM pad; ASSEMBLY_OPTIONS: DNP; Barcode: 96000010; CIP Link: http://xsjbrdwin1/CIP-E/Component/Index/All?pn=96000010; MANF: DNP; MANF_P/N: DNP; OWNER: 3709; Part Type: Unassigned Part Type; PartType: TEST POINT; Pins: 1PIN; ROHS: Yes; Datasheet: NA
C73 = CAP_NP: Cap Cer 100pF 5% 50V C0G 0402; ALT_SYMBOLS: CAPC100X50X55RND; Agile Part Number: CAP-00020-01; Barcode: 100119; CIP Link: http://xsjbrdwin1/CIP-E/Component/Index/All?pn=100119; Dielectric Type: X7R; Manufacturer: MURATA; Manufacturer PN: GCM1555C1H101JA16D; Part Type: CERAMIC; Tolerance: 10%; Voltage: 50V
R54 = RES: Res 200K 1% 1/16W 100PPM 50V 0402; Agile Part Number: RES-00078-01; Barcode: 200041; CIP Link: http://xsjbrdwin1/CIP-E/Component/Index/All?pn=200041; Manufacturer: PANASONIC; Manufacturer PN: ERJ2RKF2003X; Part Type: SMT - 1%; Rated Power: 1/10W; Tolerance: 1%
R55 R56 R347 R348 = RES: Res 2K21 1% 1/16W 100PPM 50V 0402; ALT_SYMBOLS: (0402,C402-25,RESC100X50X40L25NRND); Agile Part Number: RES-00023-01; Barcode: 200163; CIP Link: http://xsjbrdwin1/CIP-E/Component/Index/All?pn=200163; Manufacturer: PANASONIC; Manufacturer PN: ERJ2RKF2211X; Part Type: SMT - 1%; Rated Power: 1/16W; Tolerance: 1%
R57 R62 = RES: Res 4K7 1% 1/16W 100PPM 50V 0402; ALT_SYMBOLS: RESC100X50X40RND; Agile Part Number: RES-00035-01; Barcode: 200067; CIP Link: http://xsjbrdwin1/CIP-E/Component/Index/All?pn=200067; Manufacturer: PANASONIC; Manufacturer PN: ERJ-2RKF1501X; Part Type: SMT - 1%; Rated Power: 1/16W; Tolerance: 1%
R58 R63 = RES: Res 4K7 1% 1/16W 100PPM 50V 0402; ALT_SYMBOLS: RESC100X50X40RND; Agile Part Number: RES-00035-01; Barcode: 200067; CIP Link: http://xsjbrdwin1/CIP-E/Component/Index/All?pn=200067; Manufacturer: PANASONIC; Manufacturer PN: ERJ2RKF2211X; Part Type: SMT - 1%; Rated Power: 1/16W; Tolerance: 1%
R61 R332 = RES: Res 10K 1% 1/16W 100PPM 50V 0402; ALT_SYMBOLS: RESC100X50X40RND; Agile Part Number: RES-00030-01; Barcode: 200025; CIP Link: http://xsjbrdwin1/CIP-E/Component/Index/All?pn=200025; Manufacturer: PANASONIC; Manufacturer PN: ERJ2RKF1002X; Part Type: SMT - 1%; Rated Power: 1/16W; Tolerance: 1%
R256 R349 R487 = RES: Res 1K 1% 1/16W 100PPM 50V 0402; ALT_SYMBOLS: RESC100X50X40RND; Agile Part Number: RES-00027-01; Barcode: 200098; CIP Link: http://xsjbrdwin1/CIP-E/Component/Index/All?pn=200098; Manufacturer: PANASONIC; Manufacturer PN: ERJ2RKF1001X; OWNER: 4001; PRICE: 0; Part Type: SMT - 1%; PartType: SMT - 1%; Power: 1/16W; ROHS: Yes; Rated Power: 1/16W; Tolerance: 1%; primarykey: 7
U15 U76 U85 = M24C64: IC EEPROM 64Kb 8Kx8b I2C 1MHz 1.7-5.5V TSSOP-8; Agile Part Number: ICS-00011-01; Barcode: 500635; CIP Link: http://xsjbrdwin1/CIP-E/Component/Index/All?pn=500635; Manufacturer: ST MICRO; Manufacturer PN: M24C64-DRDW8TP/K; Part Type: MEMORY
U16 = PCA9306DCTR: IC Lvl Trans Dual Bidir I2C/SM Bus 1.2-5.5V SSOP-8; Agile Part Number: ICS-00172-01; Barcode: 500219; CIP Link: http://xsjbrdwin1/CIP-E/Component/Index/All?pn=500219; Manufacturer: TEXAS INSTRUMENTS; Part Type: LEVEL TRANSLATOR
U18 = TCA9546A: IC Switch Bus 4-Ch Bidir I2C/SMBus 400KHz 1.65-5.5V 25mA 16R TSSOP-16; Agile Part Number: ICS-00265-01; Barcode: 500394; CIP Link: http://xsjbrdwin1/CIP-E/Component/Index/All?pn=500394; Manufacturer: TEXAS INSTRUMENTS; Manufacturer PN: TCA9546APWR; Part Type: MULTIPLEXER
U75 = ATSHA204A_MAHDA: IC CRYPTO 4.5KB I2C 8UDFN; Agile Part Number: ICS-00251-01; Barcode: 500374; CIP Link: http://xsjbrdwin1/CIP-E/Component/Index/All?pn=500374; Part Type: AUTHENTICATION
C400 C401 C412 C413 = CAP_NP: Cap Cer 33pF 5% 50V C0G 0402; ALT_SYMBOLS: CAPC100X50X56RND; Agile Part Number: CAP-00013-01; Barcode: 100188; CIP Link: http://xsjbrdwin1/CIP-E/Component/Index/All?pn=100188; Dielectric Type: NP0; Manufacturer: AVX; Manufacturer PN: 04025A330JAT2A; Part Type: CERAMIC; Tolerance: 5%; Voltage: 50V
J19 J20 = HDR_2X6: Conn Hdr Female RA 12 Pos 2x6 2.54mm P TH; Agile Part Number: CON-00015-01; Barcode: 390021; CIP Link: http://xsjbrdwin1/CIP-E/Component/Index/All?pn=390021; Manufacturer: SULLINS; Manufacturer PN: PPPC062LJBN-RC; OWNER: 3709; PRICE: 1.58; Part Type: HEADER; PartType: HEADER; Pins: 12PINS; Pitch: 0.100; ROHS: Yes
R306 R307 R316 R317 = RES: Res 20R 1% 1/16W 100PPM 50V 0402; ALT_SYMBOLS: RESC100X50X40RND; Agile Part Number: RES-00033-01; Barcode: 200119; CIP Link: http://xsjbrdwin1/CIP-E/Component/Index/All?pn=200119; Manufacturer: VISHAY DALE; Manufacturer PN: CRCW040220R0FKED; Part Type: SMT - 1%; Rated Power: 1/16W; Tolerance: 1%
J21 = HDR_2X20: CONN HEADER VERT 40POS 2.54MM; Agile Part Number: CON-00090-01; Barcode: 390220; CIP Link: http://xsjbrdwin1/CIP-E/Component/Index/All?pn=390220; Part Type: HEADER; Pitch: 0.100
MH11 MH12 = HOLE: MOUNTING HOLE, NON-PLATED 2.75MM HOLE; ASSEMBLY_OPTIONS: DNP; Barcode: 96000060; CIP Link: http://xsjbrdwin1/CIP-E/Component/Index/All?pn=96000060
R328 = RES: Res 10K 1% 1/16W 100PPM 50V 0402; ALT_SYMBOLS: RESC100X50X40RND; ASSEMBLY_OPTIONS: <ASSEMBLY_OPTIONS>; Agile Part Number: RES-00030-01; Barcode: 200025; CIP Link: http://xsjbrdwin1/CIP-E/Component/Index/All?pn=200025; Manufacturer: PANASONIC; Manufacturer PN: ERJ2RKF1002X; Part Type: SMT - 1%; Rated Power: 1/16W; Tolerance: 1%
R329 R333 = RES: Res 100K 1% 1/16W 100PPM 50V 0402; ALT_SYMBOLS: RESC100X50X40RND; Agile Part Number: RES-00011-01; Barcode: 200026; CIP Link: http://xsjbrdwin1/CIP-E/Component/Index/All?pn=200026; Manufacturer: PANASONIC; Manufacturer PN: ERJ2RKF1003X; Part Type: SMT - 1%; Rated Power: 1/16W; Tolerance: 1%
R330 R331 = RES: Res 3K9 1% 1/16W 100PPM 50V 0402; ALT_SYMBOLS: (0402,C402-25,RESC100X50X40L25NRND); Agile Part Number: RES-00475-01; Barcode: 200576; CIP Link: http://xsjbrdwin1/CIP-E/Component/Index/All?pn=200576; Part Type: SMT - 1%; Rated Power: 1/10W; Tolerance: 1%
U73 U74 = TPS2065CDBVT: IC Switch Power 1A 2.7-5.5V 125mR SOT23-5 Active Low; Agile Part Number: ICS-00871-01; Barcode: 50000321; CIP Link: http://xsjbrdwin1/CIP-E/Component/Index/All?pn=50000321; Part Type: LOAD SWITCH; Supply Voltage: Not Required
C432 C576 = CAP_NP: Cap Cer 22uF 20% 25V X5R 0805; Agile Part Number: CAP-00209-01; Barcode: 100281; CIP Link: http://xsjbrdwin1/CIP-E/Component/Index/All?pn=100281; Dielectric Type: X5R; Manufacturer: MURATA; Manufacturer PN: GRM21BR61E226ME44L; Part Type: CERAMIC; Tolerance: 20%; Voltage: 25V
C433 C435 = CAP_NP: Cap Cer 100nF 10% 25V X5R 0402; ALT_SYMBOLS: CAPC100X50X55RND; Agile Part Number: CAP-00068-01; CIP Link: http://xsjbrdwin1/CIP-E/Component/Index/All?pn=100040; Dielectric Type: X5R; OWNER: 4001; PRICE: 0.01; Part Type: CERAMIC; PartType: CERAMIC; ROHS: Yes; Tolerance: 10%; Voltage: 25V; barcode: 100040
C434 C575 = CAP_NP: Cap Cer 22uF 20% 25V X5R 0805; Agile Part Number: CAP-00209-01; CIP Link: http://xsjbrdwin1/CIP-E/Component/Index/All?pn=100281; Dielectric Type: X5R; OWNER: 3709; PRICE: 0.17; Part Type: CERAMIC; PartType: CERAMIC; ROHS: Yes; Tolerance: 20%; Voltage: 25V; barcode: 100281
DS9 DS10 = LED: LED Green Diffused 20mA 5V 570nm 0603; Agile Part Number: DIO-00003-01; Barcode: 300021; CIP Link: http://xsjbrdwin1/CIP-E/Component/Index/All?pn=300021; Manufacturer: LUMEX; Manufacturer PN: SML-LX0603GW-TR; Rated Power: 2.2-20MA; Voltage: 2.2V
J23 = ZSFP_PLUS_CONNECTOR_NO_CAGE: Conn Rcpt SFP+ Female RA 20 Pos 2x10 0.8mm P Black SMT; Agile Part Number: CON-00463-01; Barcode: 40000145; CIP Link: http://xsjbrdwin1/CIP-E/Component/Index/All?pn=40000145; Number of Pins: 20; Part Type: CONNECTOR
J24 = 747540101: Conn Cage Rcpt SFP+ 1x1 RA EMI Springs Press-Fit; Agile Part Number: CON-00475-01; Barcode: 90000032; CIP Link: http://xsjbrdwin1/CIP-E/Component/Index/All?pn=90000032; Part Type: Mechanical Part
L10 L11 = IND: Ind 4.7uH 20% 3.2A Irms 3.0A Isat 81.3mR 5.49x5.18mm SMT Shielded; Agile Part Number: IND-00167-01; Barcode: 500072; CIP Link: http://xsjbrdwin1/CIP-E/Component/Index/All?pn=500072; OWNER: 3709; PRICE: 1.08; Part Type: POWER INDUCTOR; PartType: POWER INDUCTOR; ROHS: Yes; Tolerance: 20%
R345 R346 = RES: Res 261R 1% 1/16W 100PPM 50V 0402; ALT_SYMBOLS: RESC100X50X40RND; Agile Part Number: RES-00086-01; Barcode: 200050; CIP Link: http://xsjbrdwin1/CIP-E/Component/Index/All?pn=200050; Manufacturer: PANASONIC; Manufacturer PN: ERJ2RKF2610X; Part Type: SMT - 1%; Rated Power: 1/16W; Tolerance: 1%

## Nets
5V0_IN: C75.1 C428.1 R7.1 R28.1 R329.1 U19.15(VDD2) U19.31(VDD) U73.5(IN) ; also on sheet 3 4 5 24 25
GND: C53.2 C64.2 C73.2 C74.2 C75.2 C329.2 C400.2 C401.2 C402.2 C403.2 C404.2 C405.2 C406.2 C407.2 C408.2 C409.2 C410.2 C411.2 C412.2 C413.2 C414.2 C415.2 C416.2 C417.2 C418.2 C419.2 C420.2 C421.2 C422.2 C423.2 C424.2 C425.2 C426.2 C427.2 C428.2 C429.2 C430.2 C431.2 C432.2 C433.2 C434.2 C435.2 C436.2 C437.2 C538.2 C539.2 C540.2 C541.2 C542.2 C543.2 C548.2 C575.2 C576.2 C577.2 C578.2 C587.2 C588.2 C589.2 C590.2 C591.2 C592.2 J19.9(P9) J19.10(P10) J20.9(P9) J20.10(P10) J21.6(P6) J21.9(P9) J21.14(P14) J21.20(P20) J21.25(P25) J21.30(P30) J21.34(P34) J21.39(P39) J22.11 J22.12 J22.13 J22.14 J22.31 J22.32 J22.37 J22.38 J22.43 J22.44 J22.49 J22.50 J22.55 J22.56 J23.1(VEET) J23.10(VEER_1) J23.11(VEER_2) J23.14(VEER_3) J23.17(VEET_2) J23.20(VEET_3) J24.1(GND1) J24.2(GND2) J24.3(GND3) J24.4(GND4) J24.5(GND5) J24.6(GND6) J24.7(GND7) J24.8(GND8) J24.9(GND9) J24.10(GND10) J24.11(GND11) J24.12(GND12) J24.13(GND13) J24.14(GND14) J24.15(GND15) J24.16(GND16) J24.17(GND17) J24.18(GND18) J24.19(GND19) J24.20(GND20) MH11.1 MH12.1 Q25.2(SOURCE) Q26.2(SOURCE) Q34.2(SOURCE) R328.2 R332.2 R343.1 R344.1 R349.2 R475.2 R476.2 R487.2 R489.2 SW2.1(SW1) U15.2(E1) U15.3(E2) U15.4(VSS) U16.1(GND) U18.1(A0) U18.2(A1) U18.8(GND) U19.14(GND1) U19.30(GND2) U19.33(EPAD1) U19.34(EPAD2) U19.35(EPAD3) U19.36(EPAD4) U73.2(GND) U74.2(GND) U75.4(GND) U76.2(E1) U76.3(E2) U76.4(VSS) U85.1(E0) U85.3(E2) U85.4(VSS) U86.3(GND) U87.3(GND) U88.3(GND) U89.3(GND) U90.3(GND) U91.4(GND) U92.2(GND) ; also on sheet 3 4 5 6 7 8 9 10 17 18 19 20 21 22 23 24 25
VCCR_SFP: C432.1 C433.1 J23.15(VCCR) L10.2
VCCT_SFP: C434.1 C435.1 J23.16(VCCT) L11.2
CC_PL_PGOOD: R28.2 U19.25(CC_PL_PGOOD) ; also on sheet 5 8
CC_PS_PGOOD: R7.2 U19.24(CC_PS_PGOOD) ; also on sheet 4 8
CC_PS_POR_B: R452.1 SW2.2(SW2)
CC_PS_POR_B_R: C548.1 R452.2 U19.23(RESET_BUTTON_B)
D_CLK_0_N: J22.60 TP48.1(TP)
D_CLK_0_P: J22.58 TP47.1(TP)
EEPROM_WC_B: R256.1 U15.7(WC_B) ; also on sheet 9
GEM2_XTAL_IN: R478.2 ; also on sheet 20
GEM2_XTAL_IN_R: R478.1 U91.8(Y1)
GEM3_XTAL_IN: R480.2 ; also on sheet 21
GEM3_XTAL_IN_R: R480.1 U91.7(Y3)
GTH_DP0_C2M_C_N: C547.2 J22.41
GTH_DP0_C2M_C_P: C546.2 J22.39
GTH_DP0_C2M_N: C547.1 ; also on sheet 7
GTH_DP0_C2M_P: C546.1 ; also on sheet 7
GTH_DP1_C2M_C_N: C545.1 J22.47
GTH_DP1_C2M_C_P: C544.1 J22.45
GTH_DP1_C2M_N: C545.2 ; also on sheet 7
GTH_DP1_C2M_P: C544.2 ; also on sheet 7
GTH_DP2_C2M_N: J23.12(RD_N) ; also on sheet 7
GTH_DP2_C2M_P: J23.13(RD_P) ; also on sheet 7
GTH_DP2_M2C_N: J23.19(TD_N) ; also on sheet 7
GTH_DP2_M2C_P: J23.18(TD_P) ; also on sheet 7
GTH_REFCLK0_C2M_N: R497.1 U90.5(OUT_N) ; also on sheet 7
GTH_REFCLK0_C2M_P: R497.2 U90.4(OUT_P) ; also on sheet 7
GTH_REFCLK1_C2M_N: R493.1 U88.5(OUT_N) ; also on sheet 7
GTH_REFCLK1_C2M_P: R493.2 U88.4(OUT_P) ; also on sheet 7
GTR_REFCLK0_C2M_N: R491.1 U87.5(OUT_N) ; also on sheet 6
GTR_REFCLK0_C2M_P: R491.2 U87.4(OUT_P) ; also on sheet 6
GTR_REFCLK1_C2M_N: R499.1 U86.5(OUT_N) ; also on sheet 6
GTR_REFCLK1_C2M_P: R499.2 U86.4(OUT_P) ; also on sheet 6
GTR_REFCLK2_C2M_N: R495.1 U89.5(OUT_N) ; also on sheet 6
GTR_REFCLK2_C2M_P: R495.2 U89.4(OUT_P) ; also on sheet 6
HDA00_CC: R347.2 U75.6(SCL) U76.6(SCL) U85.6(SCL) ; also on sheet 6
HDA01: R348.2 U75.5(SDA) U76.5(SDA) U85.5(SDA) ; also on sheet 6
HDA10: J23.8(LOS) R338.1 ; also on sheet 6
HDA19: J23.2(TX_FAULT) R336.1 ; also on sheet 6
HDB00_CC: R308.1 ; also on sheet 7
HDB01: R310.1 ; also on sheet 7
HDB02: R312.1 ; also on sheet 7
HDB03: R314.1 ; also on sheet 7
HDB04: R309.1 ; also on sheet 7
HDB05: R311.1 ; also on sheet 7
HDB06: R313.1 ; also on sheet 7
HDB07: R315.1 ; also on sheet 7
HDB08_CC: R318.1 ; also on sheet 7
HDB09: R320.1 ; also on sheet 7
HDB10: R322.1 ; also on sheet 7
HDB11: R324.1 ; also on sheet 7
HDB12: R319.1 ; also on sheet 7
HDB13: R321.1 ; also on sheet 7
HDB14: R323.1 ; also on sheet 7
HDB15: R325.1 ; also on sheet 7
HDB16_CC: J23.5(SCL) R335.1 ; also on sheet 7
HDB17: J23.4(SDA) R334.1 ; also on sheet 7
HDB18: J23.6(MOD_ABS) R339.1 ; also on sheet 7
HDB19: J23.3(TX_DISABLE) R337.1 ; also on sheet 7
HDB20: J21.18(P18) ; also on sheet 7
HDB21: J21.22(P22) ; also on sheet 7
HDB22: J21.37(P37) ; also on sheet 7
HDB23: J21.13(P13) ; also on sheet 7
HDC00_CC: J21.27(P27) R330.1 ; also on sheet 7
HDC01: J21.28(P28) R331.1 ; also on sheet 7
HDC02: J21.3(P3) R326.1 ; also on sheet 7
HDC03: J21.5(P5) R327.1 ; also on sheet 7
HDC04: J21.7(P7) ; also on sheet 7
HDC05: J21.29(P29) ; also on sheet 7
HDC06: J21.31(P31) ; also on sheet 7
HDC07: J21.26(P26) ; also on sheet 7
HDC08_CC: J21.24(P24) ; also on sheet 7
HDC09: J21.21(P21) ; also on sheet 7
HDC10: J21.19(P19) ; also on sheet 7
HDC11: J21.23(P23) ; also on sheet 7
HDC12: J21.32(P32) ; also on sheet 7
HDC13: J21.33(P33) ; also on sheet 7
HDC14: J21.8(P8) ; also on sheet 7
HDC15: J21.10(P10) ; also on sheet 7
HDC16_CC: J21.36(P36) ; also on sheet 7
HDC17: J21.11(P11) ; also on sheet 7
HDC18: J21.12(P12) ; also on sheet 7
HDC19: J21.35(P35) ; also on sheet 7
HDC20: J21.38(P38) ; also on sheet 7
HDC21: J21.40(P40) ; also on sheet 7
HDC22: J21.15(P15) ; also on sheet 7
HDC23: J21.16(P16) ; also on sheet 7
HPA05_CCN: U19.2(PL_RESET_IN1_B) ; also on sheet 6
HPA13N: Q26.1(GATE) R476.1 ; also on sheet 6
HPA13P: Q25.1(GATE) R475.1 ; also on sheet 6
HPA_CLK0P_CLK: R477.2 ; also on sheet 6
HPA_CLK0P_CLK_R: R477.1 U91.3(Y0)
HPB05_CCN: U19.3(PL_RESET_IN2_B) ; also on sheet 7
HPB10_CCP_CLK: J22.35 ; also on sheet 7
HPB11N: J22.30 ; also on sheet 7
HPB11P: J22.22 ; also on sheet 7
HPB12N: J22.26 ; also on sheet 7
HPB12P: J22.28 ; also on sheet 7
HPB13N: J22.24 ; also on sheet 7
HPB13P: J22.20 ; also on sheet 7
HPB14N: J22.15 R442.1 ; also on sheet 7
HPB14P: U19.27(PL_RESET_IN3_B) ; also on sheet 7
HPB15_CCP_CLK: J22.16 R443.1 ; also on sheet 7
HPB16N: J22.23 ; also on sheet 7
HPB16P: J22.21 ; also on sheet 7
HPB17N: J22.19 ; also on sheet 7
HPB17P: J22.29 ; also on sheet 7
HPB18N: J22.17 ; also on sheet 7
HPB18P: J22.27 ; also on sheet 7
HPB19N: J22.18 ; also on sheet 7
HPB19P: J22.25 ; also on sheet 7
HPB_CLK0P_CLK: R479.2 ; also on sheet 7
HPB_CLK0P_CLK_R: R479.1 U91.5(Y2)
I2C_SCK_LS: R55.2 U15.6(SCL) U16.6(SCL2) U18.14(SCL) U19.8(I2C_SCL) ; also on sheet 3
I2C_SDA_LS: R56.2 U15.5(SDA) U16.5(SDA2) U18.15(SDA) U19.7(I2C_SDA) ; also on sheet 3
MIO24_I2C_SCK: U16.3(SCL1) ; also on sheet 6
MIO25_I2C_SDA: U16.4(SDA1) ; also on sheet 6
MIO76: U19.4(PS_RESET_IN1_B) ; also on sheet 6
MIO77: U19.5(PS_RESET_IN2_B) ; also on sheet 6
OSC_25M_CLK: R501.2 U91.1(CLKIN)
OSC_25M_CLK_R: R501.1 U92.3(OUT)
OSC_25M_OE: R500.2 U92.1(OE)
OSC_26M_OE: R494.2 U89.1(OE)
OSC_27M_OE: R498.2 U86.1(OE)
OSC_74M25_OE: R492.2 U88.1(OE)
OSC_125M_OE: R490.2 U87.1(OE)
OSC_156M25_OE: R496.2 U90.1(OE)
PL_1V8: C538.1 C539.1 C543.1 C591.1 C592.1 J22.2 J22.4 Q33.2(SOURCE) R442.2 R443.2 R446.1 R486.1 R488.1 R500.1 R507.1 U91.6(VDD) U92.4(VDD) ; also on sheet 5 6 7 20 21
PL_3V3: C430.1 C436.1 C437.1 C575.1 C576.1 C577.1 C588.1 C590.1 L10.1 L11.1 R333.1 R334.2 R335.2 R336.2 R337.2 R338.2 R339.2 R341.2 R342.2 R347.1 R348.1 R492.1 R496.1 U74.5(IN) U75.8(VCC) U76.1(E0) U76.8(VCC) U85.2(E1) U85.8(VCC) U88.6(VCC) U90.6(VCC) ; also on sheet 5 6 7 10 20 21
PL_3V8: C540.1 C541.1 C542.1 J22.1 J22.3 ; also on sheet 5
PL_FRAMOS_OD_RESET_B: Q34.1(GATE) R486.2 U19.17(PL_RESET_OUT3_B)
PL_FRAMOS_RESET_B: J22.33 Q33.3(DRAIN) R489.1
PL_GEM2_RESET_B: U19.12(PL_RESET_OUT1_B) ; also on sheet 20
PL_GEM3_RESET_B: U19.13(PL_RESET_OUT2_B) ; also on sheet 21
PL_RESET_OUT4_B_NC: U19.16(PL_RESET_OUT4_B)
PMOD3_IO1_HDB00_CC: C402.1 J19.1(P1) R306.2 R308.2
PMOD3_IO2_HDB01: C406.1 J19.3(P3) R310.2
PMOD3_IO3_HDB02: C408.1 J19.5(P5) R312.2
PMOD3_IO4_HDB03: C410.1 J19.7(P7) R314.2
PMOD3_IO5_HDB04: C403.1 J19.2(P2) R307.2 R309.2
PMOD3_IO6_HDB05: C407.1 J19.4(P4) R311.2
PMOD3_IO7_HDB06: C409.1 J19.6(P6) R313.2
PMOD3_IO8_HDB07: C411.1 J19.8(P8) R315.2
PMOD4_IO1_HDB08_CC: C414.1 J20.1(P1) R316.2 R318.2
PMOD4_IO2_HDB09: C418.1 J20.3(P3) R320.2
PMOD4_IO3_HDB10: C420.1 J20.5(P5) R322.2
PMOD4_IO4_HDB11: C422.1 J20.7(P7) R324.2
PMOD4_IO5_HDB12: C415.1 J20.2(P2) R317.2 R319.2
PMOD4_IO6_HDB13: C419.1 J20.4(P4) R321.2
PMOD4_IO7_HDB14: C421.1 J20.6(P6) R323.2
PMOD4_IO8_HDB15: C423.1 J20.8(P8) R325.2
PMOD_3V3: C404.1 C405.1 C416.1 C417.1 J19.11(P11) J19.12(P12) J20.11(P11) J20.12(P12) ; also on sheet 10
PS_1V8: C329.1 R447.1 R448.1 R449.1 R450.1 R451.1 U16.2(VREF1) ; also on sheet 4 8 9 17 18 19 24 25
PS_3V3: C53.1 C64.1 C74.1 C578.1 C587.1 C589.1 R54.1 R55.1 R56.1 R57.1 R58.1 R61.1 R62.1 R63.1 R256.2 R490.1 R494.1 R498.1 U15.1(E0) U15.8(VCC) U18.13(A2) U18.16(VCC) U86.6(VCC) U87.6(VCC) U89.6(VCC) ; also on sheet 4 17 18 19 22 24 25
PS_GEM0_RESET_B: U19.10(PS_RESET_OUT6_B) ; also on sheet 18
PS_GEM1_RESET_B: U19.29(PS_RESET_OUT7_B) ; also on sheet 19
PS_POR_B: U19.11(SOM_PS_POR_B) ; also on sheet 6 9
RPI_3V3: C424.1 C425.1 C431.1 J21.1(P1) J21.17(P17) R326.2 R327.2 R330.2 R331.2 U74.1(OUT)
RPI_3V3_EN: R332.1 U74.4(EN)
RPI_3V3_PWR_FLT_B: R333.2 U74.3(FLT_B)
RPI_5V0: C426.1 C427.1 C429.1 J21.2(P2) J21.4(P4) U73.1(OUT)
RPI_5V0_EN: R328.1 U73.4(EN)
RPI_5V_PWR_FLT_B: R329.2 U73.3(FLT_B)
SD_CTRLR_RESET_B: U19.18(PS_RESET_OUT3_B) ; also on sheet 22
SFP_RS0: J23.7(RS0) R341.1 R343.2
SFP_RS1: J23.9(RS1) R342.1 R344.2
USB0_HUB_I2C_SCK: R57.2 U18.5(SC0) ; also on sheet 24
USB0_HUB_I2C_SDA: R62.2 U18.4(SD0) ; also on sheet 24
USB0_HUB_RESET_B: U19.1(PS_RESET_OUT4_B) ; also on sheet 24
USB0_PHY_RESET_B: U19.28(PS_RESET_OUT1_B) ; also on sheet 24
USB1_HUB_I2C_SCK: R58.2 U18.7(SC1) ; also on sheet 25
USB1_HUB_I2C_SDA: R63.2 U18.6(SD1) ; also on sheet 25
USB1_HUB_RESET_B: U19.32(PS_RESET_OUT5_B) ; also on sheet 25
USB1_PHY_RESET_B: U19.19(PS_RESET_OUT2_B) ; also on sheet 25
UTIL_3V3: DS9.2 DS10.2 ; also on sheet 3 8
N3441577: C400.1 R306.1
N3441589: C401.1 R307.1
N3442529: C412.1 R316.1
N3442541: C413.1 R317.1
N3463703: C73.1 R54.2 U16.7(VREF2) U16.8(EN)
N3465992: R61.2 U18.3(RESET_B)
N3638229: R349.1 U76.7(WC_B)
N3638972: Q25.3(DRAIN) R345.1
N3638976: DS9.1 R345.2
N3639084: Q26.3(DRAIN) R346.1
N3639088: DS10.1 R346.2
N3854583: R451.2 U19.6(PS_RESET_IN3_B)
N3854590: R450.2 U19.9(PS_RESET_IN4_B)
N3854613: R449.2 U19.20(PS_RESET_IN5_B)
N3854620: R448.2 U19.21(PS_RESET_IN6_B)
N3854627: R447.2 U19.22(PS_RESET_IN7_B)
N3854951: R446.2 U19.26(PL_RESET_IN4_B)
N4252518: J22.5 TP41.1(TP)
N4252522: J22.7 TP43.1(TP)
N4252526: J22.9 TP45.1(TP)
N4252662: J22.6 TP42.1(TP)
N4252666: J22.8 TP44.1(TP)
N4252670: J22.10 TP46.1(TP)
N4424560: Q33.1(GATE) Q34.3(DRAIN) R488.2
N4546556: R487.1 U85.7(WC_B)
N4939590: R507.2 U91.2(OE/1G)

Not connected (* = marked no-connect by the designer): J22 34* 36* 40* 42* 46* 48* 51* 52* 53* 54* 57* 59*; U18 9(SD2)* 10(SC2)* 11(SD3)* 12(SC3)*; U75 1(NC)* 2(NC)* 3(NC)* 7(NC)*; U86 2(NC)*; U87 2(NC)*; U88 2(NC)*; U89 2(NC)*; U90 2(NC)*

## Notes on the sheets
sheet 11
- PMOD #3
- Place close to
  SOM Connector
- Place close to
  PMOD Connector
- Place close to
  SOM Connector
- Place close to
  PMOD Connector
- PMOD #4
- Place close to
  SOM Connector
- Place close to
  PMOD Connector
- Place close to
  SOM Connector
- Place close to
  PMOD Connector
sheet 12
- Raspberry Pi Expansion Header
- RPI_GPIO2_SDA
- RPI_GPIO3_SCL
- RPI_GPIO4_GPCLK0
- RPI_GPIO14_TXD
- RPI_GPIO15_RXD
- RPI_GPIO17
- RPI_GPIO18_PCM_CLK
- RPI_GPIO27
- RPI_GPIO22
- RPI_GPIO23
- RPI_GPIO24
- RPI_GPIO10_MOSI
- RPI_GPIO9_MISO
- RPI_GPIO25
- RPI_GPIO11_SCLK
- RPI_GPIO8_CE0
- RPI_GPIO7_CE1
- RPI_GPIO0_ID_SD
- RPI_GPIO1_ID_SC
- RPI_GPIO5
- RPI_GPIO6
- RPI_GPIO12_PWM0
- RPI_GPIO13_PWM1
- RPI_GPIO19_PCM_FS
- RPI_GPIO16
- RPI_GPIO26
- RPI_GPIO20_PCM_DIN
- RPI_GPIO21_PCM_DOUT
sheet 13
- Framos FPA SLVS-EC
- I2C_SDA SPI_MOSI
- I2C_SCL SPI_SCK
- GPIO15 SPI_MISO
- GPIO17 SPI_CS
- GPIO11 TOUT0
- GPIO8 TOUT1
- GPIO6 SLAMODE
- GPIO9 TOUT2
- GPIO0 XMASTER0
- GPIO7 XTRIG2
- GPIO14
- GPIO16
- GPIO2 XHS0
- GPIO3 XTRIG0
- GPIO10
- GPIO1 XVS0
- RST0
- MCLK0
- D_DATA_0_P
- D_DATA_0_N
- Place AC caps closer to Framos connector
- D_DATA_1_P
- D_DATA_1_N
- D_CLK_0_P
- D_CLK_0_N
- Place AC caps closer to Framos connector
- SLVS-EC (2 Lanes) Interface
sheet 14
- SFP+ Connector
- DC Block on Module
- FULL BW RX
- FULL BW TX
- LOW BW RX
- LOW BW TX
- SFP+ Cage
- SFP+ LEDs
- LED1
- Default: OFF
  High: ON
  Low: OFF
- LED2
sheet 15
- MIO I2C LEVEL SHIFTER
- Euresys IP
  Authentication Device
- I2C ADDRESS IS PROGRAMMABLE
  DEFAULT ADDRESS IS 0x64
- Euresys IP
  EEPROM
- SYSTEM EEPROM
- EEPROM ADDRESS:
  0x51 and 0x59
- EtherCAT IP
  EEPROM
- EEPROM ADDRESS:
  0x51 and 0x59
- MIO I2C SWITCH
- EEPROM ADDRESS:
  0x52 and 0x5A
- I2C ADDR = 0x74
sheet 16
- RESET LOGIC
- RESET
  BUTTON
- I2C ADDR: 0x10 and 0x11
- Oscillator:
  125 MHz LVDS (GTR GEM0)
- VALUE/DNP TBD
- Placed close to JA1 if possible
- Oscillator:
  74.25  MHz LVDS (GTH SLVS-EC)
- Placed close to JA2 if possible
- Oscillator:
  26  MHz LVDS (GTR USB)
- VALUE/DNP TBD
- Placed close to JA1 if possible
- Oscillator:
  156.25 MHz LVDS (GTH SFP+)
- Placed close to JA2 if possible
- Oscillator:
  27  MHz LVDS (GTR DP)
- VALUE/DNP TBD
- Placed close to JA1 if possible
- Oscillator:
  25  MHz LVCMOS (PL GEM2&3)
